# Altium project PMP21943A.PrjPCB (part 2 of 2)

## Sheet PMP21943A-Bias.SchDoc: Bias Supply
size 431 x 279 mm; Date: Not shown in title block; ApprovedBy: Not shown in title block; CheckedBy: Not shown in title block; Author: Not shown in title block; CompanyName: Not shown in title block; Engineer: Not shown in title block; Organization: Not shown in title block; Address1: Not shown in title block; Address2: Not shown in title block; Address3: Not shown in title block; Address4: Not shown in title block; DocumentNumber: 2; Revision: Use project parameter SCH_Rev; SheetNumber: 2; SheetTotal: 7; PageSetup: Record=PageOptions¦CenterHorizontal=True¦CenterVertical=True¦PrintScale=1.00¦XCorrection=1.00¦YCorrection=1.00¦PrintKind=0¦BorderSize=5000000¦LeftOffset=0¦BottomOffset=0¦Orientation=2¦PaperLength=1000¦PaperWidth=1000¦Scale=100¦PaperSource=15¦PrintQuality=600¦MediaType=1¦DitherType=10¦PaperKind=Letter¦PrintScaleMode=1
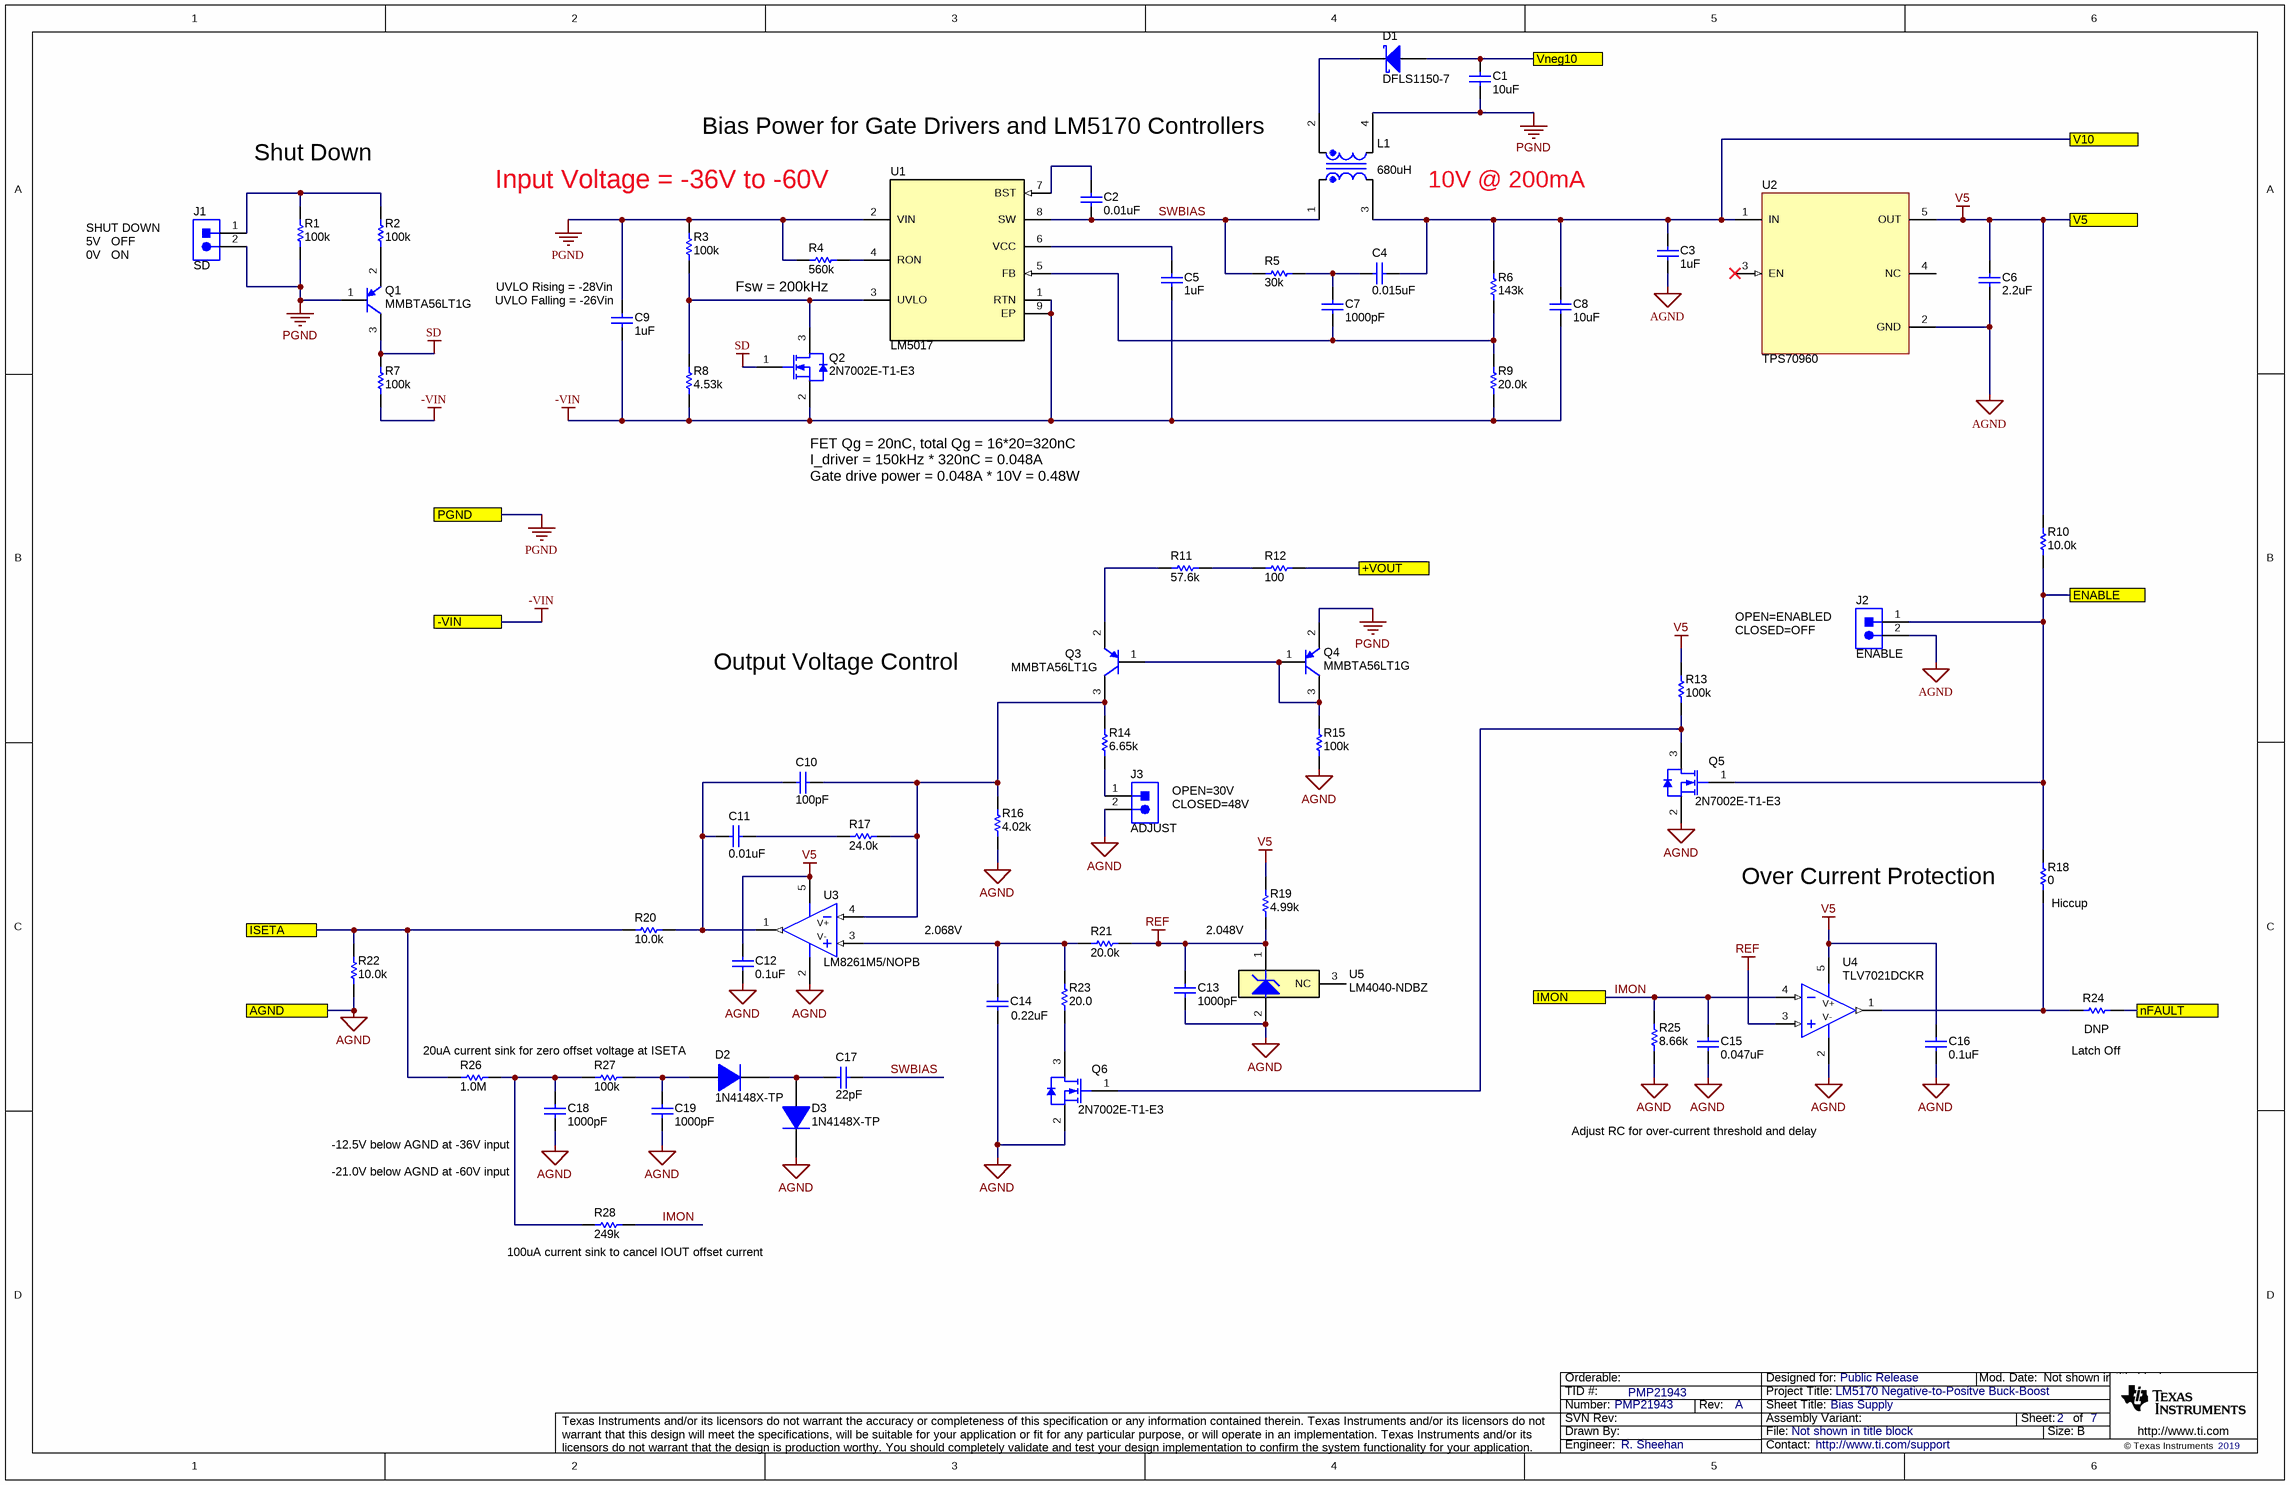
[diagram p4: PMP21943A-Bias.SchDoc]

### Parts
C1  ValueDisplayed: 10uF  [0805L]  (hidden comment: Capacitor)
C2  ValueDisplayed: 0.01uF  [0603L]  (hidden comment: Capacitor)
C3  ValueDisplayed: 1uF  [0805_HV]  (hidden comment: Capacitor)
C4  ValueDisplayed: 0.015uF  [0603L]  (hidden comment: Capacitor)
C5  ValueDisplayed: 1uF  [0603L]  (hidden comment: Capacitor)
C6  ValueDisplayed: 2.2uF  [0805_HV]  (hidden comment: Capacitor)
C7  ValueDisplayed: 1000pF  [0603L]  (hidden comment: Capacitor)
C8  ValueDisplayed: 10uF  [0805L]  (hidden comment: Capacitor)
C9  ValueDisplayed: 1uF  [1210_180L]  (hidden comment: Capacitor)
C10  ValueDisplayed: 100pF  [0603L]  (hidden comment: Capacitor)
C11  ValueDisplayed: 0.01uF  [0603L]  (hidden comment: Capacitor)
C12  ValueDisplayed: 0.1uF  [0603L]  (hidden comment: Capacitor)
C13  ValueDisplayed: 1000pF  [0603L]  (hidden comment: GRM188R72A102KA01D)
C14  ValueDisplayed: 0.22uF  [0603]  (hidden comment: C1608X7R1H224K080AB)
C15  ValueDisplayed: 0.047uF  [0603L]  (hidden comment: Capacitor)
C16  ValueDisplayed: 0.1uF  [0603L]  (hidden comment: Capacitor)
C17  ValueDisplayed: 22pF  [0603L]  (hidden comment: Capacitor)
C18  ValueDisplayed: 1000pF  [0603L]  (hidden comment: GRM188R72A102KA01D)
C19  ValueDisplayed: 1000pF  [0603L]  (hidden comment: GRM188R72A102KA01D)
D1  DFLS1150-7  [PowerDI123]
D2  1N4148X-TP  [SOD-523]
D3  1N4148X-TP  [SOD-523]
J1  SD  [Samtec_HTSW-102-07-G-S]
J2  ENABLE  [Samtec_HTSW-102-07-G-S]
J3  ADJUST  [Samtec_HTSW-102-07-G-S]
L1  ValueDisplayed: 680uH  [DRQ74]  (hidden comment: DRQ74-681-R)
Q1  MMBTA56LT1G  [SOT-23L]
Q2  2N7002E-T1-E3  [SOT-23]
Q3  MMBTA56LT1G  [SOT-23L]
Q4  MMBTA56LT1G  [SOT-23L]
Q5  2N7002E-T1-E3  [SOT-23]
Q6  2N7002E-T1-E3  [SOT-23]
R1  ValueDisplayed: 100k  [0603L]  (hidden comment: Resistor)
R2  ValueDisplayed: 100k  [0603L]  (hidden comment: Resistor)
R3  ValueDisplayed: 100k  [0603L]  (hidden comment: Resistor)
R4  ValueDisplayed: 560k  [0603L]  (hidden comment: Resistor)
R5  ValueDisplayed: 30k  [0603L]  (hidden comment: Resistor)
R6  ValueDisplayed: 143k  [0603L]  (hidden comment: Resistor)
R7  ValueDisplayed: 100k  [0603L]  (hidden comment: Resistor)
R8  ValueDisplayed: 4.53k  [0603L]  (hidden comment: Resistor)
R9  ValueDisplayed: 20.0k  [0603L]  (hidden comment: Resistor)
R10  ValueDisplayed: 10.0k  [0603L]  (hidden comment: Resistor)
R11  ValueDisplayed: 57.6k  [0603L]  (hidden comment: Resistor)
R12  ValueDisplayed: 100  [0603L]  (hidden comment: Resistor)
R13  ValueDisplayed: 100k  [0603L]  (hidden comment: Resistor)
R14  ValueDisplayed: 6.65k  [0603L]  (hidden comment: Resistor)
R15  ValueDisplayed: 100k  [0603L]  (hidden comment: Resistor)
R16  ValueDisplayed: 4.02k  [0603L]  (hidden comment: Resistor)
R17  ValueDisplayed: 24.0k  [0603L]  (hidden comment: Resistor)
R18  ValueDisplayed: 0  [0603L]  (hidden comment: Resistor)
R19  ValueDisplayed: 4.99k  [0603L]  (hidden comment: Resistor)
R20  ValueDisplayed: 10.0k  [0603L]  (hidden comment: Resistor)
R21  ValueDisplayed: 20.0k  [0603L]  (hidden comment: Resistor)
R22  ValueDisplayed: 10.0k  [0603L]  (hidden comment: Resistor)
R23  ValueDisplayed: 20.0  [0603L]  (hidden comment: Resistor)
R24  DNP  [0603L]
R25  ValueDisplayed: 8.66k  [0603L]  (hidden comment: Resistor)
R26  ValueDisplayed: 1.0M  [0603L]  (hidden comment: Resistor)
R27  ValueDisplayed: 100k  [0603L]  (hidden comment: Resistor)
R28  ValueDisplayed: 249k  [0603L]  (hidden comment: Resistor)
U1  LM5017  [DDA0008B_L]
U2  TPS70960  [DBV0005A_N]
U3  LM8261M5/NOPB  [DBV0005A_N]
U4  TLV7021DCKR  [DCK0005A_N]
U5  LM4040-NDBZ  [DBZ0003A_N]

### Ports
+VOUT, -VIN, AGND, ENABLE, IMON, ISETA, nFAULT, PGND, V5, V10, Vneg10

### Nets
+VOUT: R12.1 ; port +VOUT
-VIN: C5.2 C8.2 C9.2 Q2.2(S) R7.1 R8.2 R9.1 U1.1(RTN) U1.9(EP) ; port -VIN
AGND: C3.2 C6.2 C12.2 C13.2 C14.2 C15.2 C16.1 C18.2 C19.2 D3.1(K) J2.2 J3.2 Q5.2(S) Q6.2(S) R15.2 R16.2 R22.2 R25.1 U2.2(GND) U3.2(V-) U4.2(V-) U5.2(A) ; port AGND
PGND: C1.2 C9.1 J1.2 L1.4 Q1.1(B) Q4.2(E) R1.1 R3.1 R4.1 U1.2(VIN) ; port PGND
REF: C13.1 R19.2 R21.1 U4.3(IN+) U5.1(K)
SD: Q1.3(C) Q2.1(G) R7.2
V5: C6.1 C12.1 C16.2 R10.2 R13.1 R19.1 U2.5(OUT) U3.5(V+) U4.5(V+) ; port V5
V10: C3.1 C4.2 C8.1 L1.3 R6.2 U2.1(IN) ; port V10
ENABLE: J2.1 Q5.1(G) R10.1 R18.2 ; port ENABLE
IMON: C15.1 R25.2 R28.2 U4.4(IN-) ; port IMON
ISETA: R20.1 R22.1 R26.1 ; port ISETA
nFAULT: R24.1 ; port nFAULT
SWBIAS: C2.2 C17.1 L1.1 R5.2 U1.8(SW)
Vneg10: C1.1 D1.2(A) ; port Vneg10
NetC2_1: C2.1 U1.7(BST)
NetC4_1: C4.1 C7.2 R5.1
NetC5_1: C5.1 U1.6(VCC)
NetC7_1: C7.1 R6.1 R9.2 U1.5(FB)
NetC10_1: C10.1 Q3.3(C) R14.1 R16.1 R17.1 U3.4(IN-)
NetC10_2: C10.2 C11.1 R20.2 U3.1(OUT)
NetC11_2: C11.2 R17.2
NetC14_1: C14.1 R21.2 R23.2 U3.3(IN+)
NetC17_2: C17.2 D2.1(K) D3.2(A)
NetC18_1: C18.1 R26.2 R27.1 R28.1
NetC19_1: C19.1 D2.2(A) R27.2
NetD1_1: D1.1(K) L1.2
NetJ1_1: J1.1 R1.2 R2.2
NetJ3_1: J3.1 R14.2
NetQ1_2: Q1.2(E) R2.1
NetQ2_3: Q2.3(D) R3.2 R8.1 U1.3(UVLO)
NetQ3_1: Q3.1(B) Q4.1(B) Q4.3(C) R15.1
NetQ3_2: Q3.2(E) R11.2
NetQ5_3: Q5.3(D) Q6.1(G) R13.2
NetQ6_3: Q6.3(D) R23.1
NetR4_2: R4.2 U1.4(RON)
NetR11_1: R11.1 R12.2
NetR18_1: R18.1 R24.2 U4.1(OUT)

Not connected (* = marked no-connect by the designer): U2 3(EN)* 4(NC); U5 3(NC)

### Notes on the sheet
- Shut Down
- Bias Power for Gate Drivers and LM5170 Controllers
- Input Voltage = -36V to -60V
- 10V @ 200mA
- (near J1) SHUT DOWN
  5V   OFF
  0V   ON
- (near C9) UVLO Rising = -28Vin
- (near C9) UVLO Falling = -26Vin
- (near R4) Fsw = 200kHz
- FET Qg = 20nC, total Qg = 16*20=320nC
  I_driver = 150kHz * 320nC = 0.048A
  Gate drive power = 0.048A * 10V = 0.48W
- Output Voltage Control
- OPEN=ENABLED
  CLOSED=OFF
- OPEN=30V
  CLOSED=48V
- (near R18) Over Current Protection
- (near R18) Hiccup
- 2.068V
- (near R19) 2.048V
- 20uA current sink for zero offset voltage at ISETA
- (near R24) Latch Off
- -12.5V below AGND at -36V input
- -21.0V below AGND at -60V input
- Adjust RC for over-current threshold and delay
- (near R28) 100uA current sink to cancel IOUT offset current

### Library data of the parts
C1 C8 = CMP-0007995-2: CAP, CERM, 10 uF, 16 V, +/- 10%, X7R, 0805; PartNumber: CL21B106KOQNNNE; Manufacturer: Samsung Electro-Mechanics; Polarized: N; Value: 10uF; U/M: EA; Cap_F: 10µF; Value1: Unknown; VDC_V: 16V; TaMin_C: -55°C; TaMax_C: 125°C; Cap_Case: 0805; AEC Category: Q200; SizeArea_mm2: 2.5; SizeAreaWB_mm2: 6.75; SizeX_mm: 2; SizeY_mm: 1.25; SizeZ_mm: 1.45
C2 C11 = CMP-0007468-5: CAP, CERM, 0.01 uF, 100 V, +/- 10%, X7R, 0603; PartNumber: GRM188R72A103KA01D; Manufacturer: MuRata; Polarized: N; Value: 0.01uF; U/M: EA; Cap_F: 10nF; Value1: Unknown; VDC_V: 100V; TaMin_C: -55°C; TaMax_C: 125°C; Cap_Case: 0603; AEC Category: Q200; SizeArea_mm2: 1.28; SizeAreaWB_mm2: 4.68; SizeX_mm: 1.6; SizeY_mm: 0.8; SizeZ_mm: 1
C3 = CMP-0007891-2: CAP, CERM, 1 uF, 100 V, +/- 10%, X7S, 0805; PartNumber: C2012X7S2A105K125AB; Manufacturer: TDK; Polarized: N; Value: 1uF; U/M: EA; Cap_F: 1µF; ESR_ohm: 8.255m; Value1: 0.008255 ohm; VDC_V: 100V; IRMS_A: 2.27442A; TaMin_C: -55°C; TaMax_C: 125°C; Cap_Case: 0805; AEC Category: Q200; SizeArea_mm2: 2.5; SizeAreaWB_mm2: 6.75; SizeX_mm: 2; SizeY_mm: 1.25; SizeZ_mm: 1.45
C4 = CMP-0006883-4: CAP, CERM, 0.015 uF, 100 V, +/- 10%, X7R, 0603; PartNumber: C0603C153K1RACTU; Manufacturer: Kemet; Polarized: N; U/M: EA; Cap_F: 15nF; Value1: Unknown; VDC_V: 100V; TaMin_C: -55°C; TaMax_C: 125°C; Cap_Case: 0603; AEC Category: Q200; SizeArea_mm2: 1.28; SizeAreaWB_mm2: 4.68; SizeX_mm: 1.6; SizeY_mm: 0.8; SizeZ_mm: 1
C5 = CMP-0007379-4: CAP, CERM, 1 uF, 16 V, +/- 10%, X7R, 0603; PartNumber: GRM188R71C105KA12D; Manufacturer: MuRata; Polarized: N; Value: 1uF; U/M: EA; Cap_F: 1µF; ESR_ohm: 0.011; Value1: 0.011 ohm; VDC_V: 16V; TaMin_C: -55°C; TaMax_C: 125°C; Cap_Case: 0603; AEC Category: Q200; SizeArea_mm2: 1.28; SizeAreaWB_mm2: 4.68; SizeX_mm: 1.6; SizeY_mm: 0.8; SizeZ_mm: 1
C6 = CMP-0007867-2: CAP, CERM, 2.2 uF, 16 V, +/- 10%, X7R, 0805; PartNumber: C2012X7R1C225K125AB; Manufacturer: TDK; Polarized: N; Value: 2.2uF; U/M: EA; Cap_F: 2.2µF; ESR_ohm: 4.9m; Value1: 0.0049 ohm; VDC_V: 16V; TaMin_C: -55°C; TaMax_C: 125°C; Cap_Case: 0805; AEC Category: Q200; SizeArea_mm2: 2.5; SizeAreaWB_mm2: 6.75; SizeX_mm: 2; SizeY_mm: 1.25; SizeZ_mm: 1.45
C7 = CMP-0007467-4: CAP, CERM, 1000 pF, 100 V, +/- 10%, X7R, 0603; PartNumber: GRM188R72A102KA01D; Manufacturer: MuRata; Polarized: N; Value: 1000pF; U/M: EA; Cap_F: 1nF; Value1: Unknown; VDC_V: 100V; TaMin_C: -55°C; TaMax_C: 125°C; Cap_Case: 0603; AEC Category: Q200; SizeArea_mm2: 1.28; SizeAreaWB_mm2: 4.68; SizeX_mm: 1.6; SizeY_mm: 0.8; SizeZ_mm: 1
C9 = CMP-0009180-2: CAP, CERM, 1 uF, 100 V, +/- 10%, X7R, 1210; PartNumber: GRM32CR72A105KA35L; Manufacturer: MuRata; Polarized: N; Value: 1uF; U/M: EA; Cap_F: 1µF; Value1: Unknown; VDC_V: 100V; TaMin_C: -55°C; TaMax_C: 125°C; Cap_Case: 1210; AEC Category: Q200; SizeArea_mm2: 8; SizeAreaWB_mm2: 14.7; SizeX_mm: 3.2; SizeY_mm: 2.5; SizeZ_mm: 1.8
C10 = CMP-0006841-4: CAP, CERM, 100 pF, 50 V, +/- 5%, C0G/NP0, 0603; PartNumber: C0603C101J5GACTU; Manufacturer: Kemet; Polarized: N; Value: 100pF; U/M: EA; Value1: Unknown; VDC_V: 50V; TaMin_C: -55°C; TaMax_C: 125°C; Cap_Case: 0603; SizeArea_mm2: 1.28; SizeAreaWB_mm2: 4.68; SizeX_mm: 1.6; SizeY_mm: 0.8; SizeZ_mm: 1; AEC Category: Q200
C12 C16 = CMP-0007469-4: CAP, CERM, 0.1 uF, 100 V, +/- 10%, X7R, 0603; PartNumber: GRM188R72A104KA35D; Manufacturer: MuRata; Polarized: N; Value: 0.1uF; U/M: EA; Cap_F: 100nF; Value1: Unknown; VDC_V: 100V; TaMin_C: -55°C; TaMax_C: 125°C; Cap_Case: 0603; AEC Category: Q200; SizeArea_mm2: 1.28; SizeAreaWB_mm2: 4.68; SizeX_mm: 1.6; SizeY_mm: 0.8; SizeZ_mm: 1
C13 C18 C19 = CMP-0007467-4: CAP, CERM, 1000 pF, 100 V, +/- 10%, X7R, 0603; Manufacturer: MuRata; Polarized: N; Value: 1000pF; U/M: EA; Cap_F: 1nF; Value1: Unknown; VDC_V: 100V; TaMin_C: -55°C; TaMax_C: 125°C; Cap_Case: 0603; AEC Category: Q200; SizeArea_mm2: 1.28; SizeAreaWB_mm2: 4.68; SizeX_mm: 1.6; SizeY_mm: 0.8; SizeZ_mm: 1
C14 = CMP-0007047-4: CAP, CERM, 0.22 uF, 50 V, +/- 10%, X7R, 0603; Manufacturer: TDK; Polarized: N; Value: 0.22uF; U/M: EA; Cap_F: 220nF; ESR_ohm: 0.021699; Value1: 0.021699 ohm; VDC_V: 50V; IRMS_A: 1.12496A; TaMin_C: -55°C; TaMax_C: 125°C; AEC Category: Q200; SizeArea_mm2: 1.28; SizeAreaWB_mm2: 4.68; SizeX_mm: 1.6; SizeY_mm: 0.8; SizeZ_mm: 1
C15 = CMP-0007457-4: CAP, CERM, 0.047 uF, 50 V, +/- 10%, X7R, 0603; PartNumber: GRM188R71H473KA61D; Manufacturer: MuRata; Polarized: N; U/M: EA; Cap_F: 47nF; Value1: Unknown; VDC_V: 50V; TaMin_C: -55°C; TaMax_C: 125°C; Cap_Case: 0603; SizeArea_mm2: 1.28; SizeAreaWB_mm2: 4.68; SizeX_mm: 1.6; SizeY_mm: 0.8; SizeZ_mm: 1; AEC Category: Q200
C17 = CMP-0007196-4: CAP, CERM, 22 pF, 50 V, +/- 5%, C0G/NP0, 0603; PartNumber: GRM1885C1H220JA01D; Manufacturer: MuRata; Polarized: N; Value: 22pF; U/M: EA; Value1: Unknown; VDC_V: 50V; TaMin_C: -55°C; TaMax_C: 125°C; Cap_Case: 0603; SizeArea_mm2: 1.28; SizeAreaWB_mm2: 4.68; SizeX_mm: 1.6; SizeY_mm: 0.8; SizeZ_mm: 1; AEC Category: Q200
D1 = CMP-0077034-2: Diode, Schottky, 150 V, 1 A, PowerDI123; Manufacturer: Diodes Inc.; Vf_V: 820mV; Value: 150V; Value1: 1A; Value2: 0.82V; TJmax_C: 175°C; SizeAreaWB_mm2: 13.066; SizeArea_mm2: 6.586; SizeX_mm: 3.7; SizeY_mm: 1.78; SizeZ_mm: 0.98; AEC Category: Q101; Green_Lifecycle: Active; Green_REACh: Passed
D2 D3 = CMP-0076957-3: Diode, Switching, 75 V, 0.3 A, SOD-523; Manufacturer: Micro Commercial Components; Vf_V: 1.25V; Value: 75V; Value1: 0.3A; Io_A: 300mA; TJmax_C: 150°C; AEC Category: Q101; Green_Lifecycle: Not Set; Green_REACh: Incomplete; SizeArea_mm2: 1.53; SizeAreaWB_mm2: 5.13; SizeX_mm: 1.7; SizeY_mm: 0.9; SizeZ_mm: 0.65
J1-J3 = CMP-0075483-1: Header, 100mil, 2x1, Gold, TH; PartNumber: HTSW-102-07-G-S; Manufacturer: Samtec; Green_Lifecycle: Active; Green_REACh: Passed; CNHeader: True; CT: False
L1 = CMP-0012798-2: Coupled inductor, 680 uH, 0.38 A, 5.15 ohm, SMD; Manufacturer: Coiltronics; Value: 680uH; Ind_H: 680µH; DCR_ohm: 5.15; SizeAreaWB_mm2: 92.16; SizeArea_mm2: 57.76; SizeX_mm: 7.6; SizeZ_mm: 4.45
Q1 Q3 Q4 = CMP-0000338-2: Transistor, PNP, 80 V, 0.5 A, SOT-23; Manufacturer: ON Semiconductor; CompType: BJT; PNP: 1; NPN: 0; Vceo_V: 80V; Vcesat1_V: 2.5dV; Value: 80 V; IcRated_A: 5dA; Value1: 0.5 A; TaMin_C: -55°C; TaMax_C: 150°C; U/M: EA; AEC Category: Q101; SizeArea_mm2: 7.5; SizeAreaWB_mm2: 14; SizeX_mm: 2.5; SizeY_mm: 3; SizeZ_mm: 1.1
Q2 = CMP-0000771-1: MOSFET, N-CH, 60 V, 0.24 A, SOT-23; Manufacturer: Vishay-Siliconix; Alternate Manufacturer: None; U/M: EA; ChType: N; Value: 60V; Value1: 1; Rdson45_ohm: 1.8; Value2: 0.4 nC; QgTyp_nC: 0.4; Vgs_V: 20V; IdsMax_A: 2.4dA; SizeAreaWB_mm2: 14; SizeArea_mm2: 7.5; SizeX_mm: 2.5; SizeY_mm: 3; SizeZ_mm: 1.1; AEC Category: Q101
Q5 Q6 = CMP-0000771-1: MOSFET, N-CH, 60 V, 0.24 A, SOT-23; Manufacturer: Vishay-Siliconix; Alternate Manufacturer: None; U/M: EA; ChType: N; Value: 60V; Value1: 1; Rdson45_ohm: 1.8; Value2: 0.4 nC; QgTyp_nC: 0.4; Vgs_V: 20V; IdsMax_A: 2.4dA; AEC Category: Q101; SizeArea_mm2: 7.5; SizeAreaWB_mm2: 14; SizeX_mm: 2.5; SizeY_mm: 3; SizeZ_mm: 1.1
R1 R2 R7 R15 = CMP-0025698-4: RES, 100 k, 5%, 0.1 W, AEC-Q200 Grade 0, 0603; PartNumber: CRCW0603100KJNEA; Manufacturer: Vishay-Dale; Value: 100k; Power_W: 100mW; Value2: 0.1W; VDC_V: 75V; TempCo: 200 ppm/C; EIA_Code: E24; AEC Category: Q200; AEC Qualified: Y; AEC Grade: 0; SizeArea_mm2: 1.28; SizeX_mm: 1.6; SizeY_mm: 0.8; SizeZ_mm: 1
R3 R13 = CMP-0021990-4: RES, 100 k, 1%, 0.1 W, AEC-Q200 Grade 0, 0603; PartNumber: CRCW0603100KFKEA; Manufacturer: Vishay-Dale; Value: 100k; Power_W: 100mW; Value2: 0.1W; VDC_V: 75V; TempCo: 100 ppm/C; EIA_Code: E96; AEC Category: Q200; AEC Qualified: Y; AEC Grade: 0; SizeArea_mm2: 1.28; SizeX_mm: 1.6; SizeY_mm: 0.8; SizeZ_mm: 1
R4 = CMP-0022496-4: RES, 560 k, 1%, 0.1 W, AEC-Q200 Grade 0, 0603; PartNumber: CRCW0603560KFKEA; Manufacturer: Vishay-Dale; Value: 560k; Power_W: 100mW; Value2: 0.1W; VDC_V: 75V; TempCo: 100 ppm/C; AEC Category: Q200; AEC Qualified: Y; AEC Grade: 0; SizeArea_mm2: 1.28; SizeX_mm: 1.6; SizeY_mm: 0.8; SizeZ_mm: 1
R5 = CMP-0025782-4: RES, 30 k, 5%, 0.1 W, AEC-Q200 Grade 0, 0603; PartNumber: CRCW060330K0JNEA; Manufacturer: Vishay-Dale; Value: 30k; Value_Code: 30k0; Power_W: 100mW; Value2: 0.1W; VDC_V: 75V; TempCo: 200 ppm/C; EIA_Code: E24; AEC Category: Q200; AEC Qualified: Y; AEC Grade: 0; SizeArea_mm2: 1.28; SizeX_mm: 1.6; SizeY_mm: 0.8; SizeZ_mm: 1
R6 = CMP-0022050-4: RES, 143 k, 1%, 0.1 W, AEC-Q200 Grade 0, 0603; PartNumber: CRCW0603143KFKEA; Manufacturer: Vishay-Dale; Value: 143k; Power_W: 100mW; Value2: 0.1W; VDC_V: 75V; TempCo: 100 ppm/C; EIA_Code: E96; AEC Category: Q200; AEC Qualified: Y; AEC Grade: 0; SizeArea_mm2: 1.28; SizeX_mm: 1.6; SizeY_mm: 0.8; SizeZ_mm: 1
R8 = CMP-0022454-4: RES, 4.53 k, 1%, 0.1 W, AEC-Q200 Grade 0, 0603; PartNumber: CRCW06034K53FKEA; Manufacturer: Vishay-Dale; Value: 4.53k; Value_Code: 4k53; Power_W: 100mW; Value2: 0.1W; VDC_V: 75V; TempCo: 100 ppm/C; EIA_Code: E96; AEC Category: Q200; AEC Qualified: Y; AEC Grade: 0; SizeArea_mm2: 1.28; SizeX_mm: 1.6; SizeY_mm: 0.8; SizeZ_mm: 1
R9 = CMP-0022204-4: RES, 20.0 k, 1%, 0.1 W, AEC-Q200 Grade 0, 0603; PartNumber: CRCW060320K0FKEA; Manufacturer: Vishay-Dale; Value: 20.0k; Res_ohm: 20k; Value_Code: 20k0; Power_W: 100mW; Value2: 0.1W; VDC_V: 75V; TempCo: 100 ppm/C; EIA_Code: E96; AEC Category: Q200; AEC Qualified: Y; AEC Grade: 0; SizeArea_mm2: 1.28; SizeX_mm: 1.6; SizeY_mm: 0.8; SizeZ_mm: 1
R10 R20 = CMP-0021998-4: RES, 10.0 k, 1%, 0.1 W, AEC-Q200 Grade 0, 0603; PartNumber: CRCW060310K0FKEA; Manufacturer: Vishay-Dale; Value: 10.0k; Res_ohm: 10k; Value_Code: 10k0; Power_W: 100mW; Value2: 0.1W; VDC_V: 75V; TempCo: 100 ppm/C; EIA_Code: E96; AEC Category: Q200; AEC Grade: 0; AEC Qualified: Y; SizeArea_mm2: 1.28; SizeX_mm: 1.6; SizeY_mm: 0.8; SizeZ_mm: 1
R11 = CMP-0022503-4: RES, 57.6 k, 1%, 0.1 W, AEC-Q200 Grade 0, 0603; PartNumber: CRCW060357K6FKEA; Manufacturer: Vishay-Dale; Value: 57.6k; Value_Code: 57k6; Power_W: 100mW; Value2: 0.1W; VDC_V: 75V; TempCo: 100 ppm/C; EIA_Code: E96; AEC Category: Q200; AEC Qualified: Y; AEC Grade: 0; SizeArea_mm2: 1.28; SizeX_mm: 1.6; SizeY_mm: 0.8; SizeZ_mm: 1
R12 = CMP-0021991-4: RES, 100, 1%, 0.1 W, AEC-Q200 Grade 0, 0603; PartNumber: CRCW0603100RFKEA; Manufacturer: Vishay-Dale; Value: 100; Value_Code: 100R; Power_W: 100mW; Value2: 0.1W; VDC_V: 75V; TempCo: 100 ppm/C; EIA_Code: E96; SizeArea_mm2: 1.28; SizeX_mm: 1.6; SizeY_mm: 0.8; SizeZ_mm: 1; AEC Category: Q200; AEC Qualified: Y; AEC Grade: 0
R14 = CMP-0022562-4: RES, 6.65 k, 1%, 0.1 W, AEC-Q200 Grade 0, 0603; PartNumber: CRCW06036K65FKEA; Manufacturer: Vishay-Dale; Value: 6.65k; Value_Code: 6k65; Power_W: 100mW; Value2: 0.1W; VDC_V: 75V; TempCo: 100 ppm/C; EIA_Code: E96; AEC Category: Q200; AEC Qualified: Y; AEC Grade: 0; SizeArea_mm2: 1.28; SizeX_mm: 1.6; SizeY_mm: 0.8; SizeZ_mm: 1
R16 = CMP-0022449-4: RES, 4.02 k, 1%, 0.1 W, AEC-Q200 Grade 0, 0603; PartNumber: CRCW06034K02FKEA; Manufacturer: Vishay-Dale; Value: 4.02k; Value_Code: 4k02; Power_W: 100mW; Value2: 0.1W; VDC_V: 75V; TempCo: 100 ppm/C; EIA_Code: E96; AEC Category: Q200; AEC Qualified: Y; AEC Grade: 0; SizeArea_mm2: 1.28; SizeX_mm: 1.6; SizeY_mm: 0.8; SizeZ_mm: 1
R17 = CMP-0022945-5: RES, 24.0 k, 1%, 0.1 W, 0603; PartNumber: RC0603FR-0724KL; Manufacturer: Yageo; Value: 24.0k; Res_ohm: 24k; Value_Code: 24k0; Power_W: 100mW; Value2: 0.1W; VDC_V: 75V; TempCo: 100 ppm/C; AEC Category: Q200; AEC Qualified: N; SizeArea_mm2: 1.28; SizeX_mm: 1.6; SizeY_mm: 0.8; SizeZ_mm: 1; SizeAreaWB_mm2: 4.68
R18 = CMP-0025697-4: RES, 0, 5%, 0.1 W, AEC-Q200 Grade 0, 0603; PartNumber: CRCW06030000Z0EA; Manufacturer: Vishay-Dale; Value: 0; Value_Code: 0000; Power_W: 100mW; Value2: 0.1W; VDC_V: 75V; TempCo: 200 ppm/C; EIA_Code: E24; SizeArea_mm2: 1.28; SizeX_mm: 1.6; SizeY_mm: 0.8; SizeZ_mm: 1; AEC Category: Q200; AEC Qualified: Y
R19 = CMP-0022458-4: RES, 4.99 k, 1%, 0.1 W, AEC-Q200 Grade 0, 0603; PartNumber: CRCW06034K99FKEA; Manufacturer: Vishay-Dale; Value: 4.99k; Value_Code: 4k99; Power_W: 100mW; Value2: 0.1W; VDC_V: 75V; TempCo: 100 ppm/C; EIA_Code: E96; AEC Category: Q200; AEC Grade: 0; AEC Qualified: Y; SizeArea_mm2: 1.28; SizeX_mm: 1.6; SizeY_mm: 0.8; SizeZ_mm: 1
R21 = CMP-0022204-4: RES, 20.0 k, 1%, 0.1 W, AEC-Q200 Grade 0, 0603; PartNumber: CRCW060320K0FKEA; Manufacturer: Vishay-Dale; Value: 20.0k; Res_ohm: 20k; Value_Code: 20k0; Power_W: 100mW; Value2: 0.1W; VDC_V: 75V; TempCo: 100 ppm/C; EIA_Code: E96; SizeArea_mm2: 1.28; SizeX_mm: 1.6; SizeY_mm: 0.8; SizeZ_mm: 1; AEC Category: Q200; AEC Qualified: Y; AEC Grade: 0
R22 = CMP-0021998-4: RES, 10.0 k, 1%, 0.1 W, AEC-Q200 Grade 0, 0603; PartNumber: CRCW060310K0FKEA; Manufacturer: Vishay-Dale; Value: 10.0k; Res_ohm: 10k; Value_Code: 10k0; Power_W: 100mW; Value2: 0.1W; VDC_V: 75V; TempCo: 100 ppm/C; EIA_Code: E96; AEC Category: Q200; AEC Qualified: Y; AEC Grade: 0; SizeArea_mm2: 1.28; SizeX_mm: 1.6; SizeY_mm: 0.8; SizeZ_mm: 1
R23 = CMP-0022206-4: RES, 20.0, 1%, 0.1 W, AEC-Q200 Grade 0, 0603; PartNumber: CRCW060320R0FKEA; Manufacturer: Vishay-Dale; Value: 20.0; Res_ohm: 20; Value_Code: 20R0; Power_W: 100mW; Value2: 0.1W; VDC_V: 75V; TempCo: 100 ppm/C; EIA_Code: E96; AEC Category: Q200; AEC Grade: 0; AEC Qualified: Y; SizeArea_mm2: 1.28; SizeX_mm: 1.6; SizeY_mm: 0.8; SizeZ_mm: 1
R24 = CMP-0025697-4: RES, 0, 5%, 0.1 W, AEC-Q200 Grade 0, 0603; PartNumber: CRCW06030000Z0EA; Manufacturer: Vishay-Dale; CompType: Resistor; Value: 0; Value_Code: 0000; Power_W: 100mW; Value2: 0.1W; VDC_V: 75V; TempCo: 200 ppm/C; EIA_Code: E24; SizeArea_mm2: 1.28; SizeX_mm: 1.6; SizeY_mm: 0.8; SizeZ_mm: 1; AEC Category: Q200; AEC Qualified: Y
R25 = CMP-0022637-4: RES, 8.66 k, 1%, 0.1 W, AEC-Q200 Grade 0, 0603; PartNumber: CRCW06038K66FKEA; Manufacturer: Vishay-Dale; Value: 8.66k; Value_Code: 8k66; Power_W: 100mW; Value2: 0.1W; VDC_V: 75V; TempCo: 100 ppm/C; EIA_Code: E96; SizeArea_mm2: 1.28; SizeX_mm: 1.6; SizeY_mm: 0.8; SizeZ_mm: 1; AEC Category: Q200; AEC Qualified: Y; AEC Grade: 0
R26 = CMP-0025736-4: RES, 1.0 M, 5%, 0.1 W, AEC-Q200 Grade 0, 0603; PartNumber: CRCW06031M00JNEA; Manufacturer: Vishay-Dale; Value: 1.0Meg; Res_ohm: 1M; Value_Code: 1M00; Power_W: 100mW; Value2: 0.1W; VDC_V: 75V; TempCo: 200 ppm/C; EIA_Code: E24; SizeArea_mm2: 1.28; SizeX_mm: 1.6; SizeY_mm: 0.8; SizeZ_mm: 1; AEC Category: Q200; AEC Qualified: Y; AEC Grade: 0
R27 = CMP-0021990-4: RES, 100 k, 1%, 0.1 W, AEC-Q200 Grade 0, 0603; PartNumber: CRCW0603100KFKEA; Manufacturer: Vishay-Dale; Value: 100k; Power_W: 100mW; Value2: 0.1W; VDC_V: 75V; TempCo: 100 ppm/C; EIA_Code: E96; SizeArea_mm2: 1.28; SizeX_mm: 1.6; SizeY_mm: 0.8; SizeZ_mm: 1; AEC Category: Q200; AEC Qualified: Y; AEC Grade: 0
R28 = CMP-0022234-4: RES, 249 k, 1%, 0.1 W, AEC-Q200 Grade 0, 0603; PartNumber: CRCW0603249KFKEA; Manufacturer: Vishay-Dale; Value: 249k; Power_W: 100mW; Value2: 0.1W; VDC_V: 75V; TempCo: 100 ppm/C; EIA_Code: E96; SizeArea_mm2: 1.28; SizeX_mm: 1.6; SizeY_mm: 0.8; SizeZ_mm: 1; AEC Category: Q200; AEC Qualified: Y; AEC Grade: 0
U1 = CMP-0066088-2: 7.5-100V Wide Vin, 300mA Constant On-Time Synchronous Buck Regulator, DDA0008B (SOIC-8); PartNumber: LM5018MRX/NOPB; Alternate PartNumber: LM5018MR/NOPB; Manufacturer: Texas Instruments; CompType: IC; U/M: EA; SizeArea_mm2: 31.0; SizeAreaWB_mm2: 57.4; SizeX_mm: 5.0; SizeY_mm: 6.2; SizeZ_mm: 1.7
U2 = CMP-0066783-1: 150-mA, 30-V, Ultra-Low IQ, Wide Input Low-Dropout Regulator with Reverse Current Protection, DBV0005A (SOT-23-5); PartNumber: TPS70950DBVR; Alternate PartNumber: TPS70950DBVT; Manufacturer: Texas Instruments; CompType: IC; U/M: EA; Green_Lifecycle: Active; Green_REACh: Passed; SizeArea_mm2: 8.12; SizeAreaWB_mm2: 14.82; SizeX_mm: 2.8; SizeY_mm: 2.9; SizeZ_mm: 1.45
U3 = CMP-0068647-3: RRIO, High Output Current & Unlimited Cap Load Op Amp, DBV0005A (SOT-23-5); Manufacturer: Texas Instruments; CompType: IC; Rating: Catalog; SizeArea_mm2: 8.12; AEC Qualified: N; SizeZ_mm: 1.45; SizeAreaWB_mm2: 14.82; SizeY_mm: 2.9; AEC Category: Q200; SizeX_mm: 2.8
U4 = CMP-0085889-2: Small-Size Micropower Low-Voltage Comparator, DCK0005A (SOT-SC70-5); Manufacturer: Texas Instruments; Alternate PartNumber: TLV7021DCKT; SizeAreaWB_mm2: 9.3; SizeY_mm: 2; Rating: Catalog; SizeZ_mm: 1.1; SizeX_mm: 2.1; CompType: IC; AEC Qualified: N; SizeArea_mm2: 4.2; AEC Category: Q200
U5 = CMP-0078976-1: Precision Micropower Shunt Voltage Reference, DBZ0003A (SOT-23-3); PartNumber: LM4040AIM3-2.0/NOPB; Manufacturer: Texas Instruments; Alternate PartNumber: LM4040AIM3X-2.0/NOPB; CompType: IC; AEC Category: Q200; AEC Qualified: N; Green_Lifecycle: Active; Green_REACh: Passed; SizeArea_mm2: 7.5; SizeAreaWB_mm2: 14; SizeX_mm: 2.5; SizeY_mm: 3; SizeZ_mm: 1.12

## Sheet PMP21943A-Controller2.SchDoc: Controller
size 431 x 279 mm; Date: Not shown in title block; ApprovedBy: Not shown in title block; CheckedBy: Not shown in title block; Author: Not shown in title block; CompanyName: Not shown in title block; Engineer: Not shown in title block; Organization: Not shown in title block; Address1: Not shown in title block; Address2: Not shown in title block; Address3: Not shown in title block; Address4: Not shown in title block; DocumentNumber: 4; Revision: Use project parameter SCH_Rev; SheetNumber: 4; SheetTotal: 7; PageSetup: Record=PageOptions¦CenterHorizontal=True¦CenterVertical=True¦PrintScale=1.00¦XCorrection=1.00¦YCorrection=1.00¦PrintKind=0¦BorderSize=5000000¦LeftOffset=0¦BottomOffset=0¦Orientation=2¦PaperLength=1000¦PaperWidth=1000¦Scale=100¦PaperSource=15¦PrintQuality=600¦MediaType=1¦DitherType=10¦PaperKind=Letter¦PrintScaleMode=1
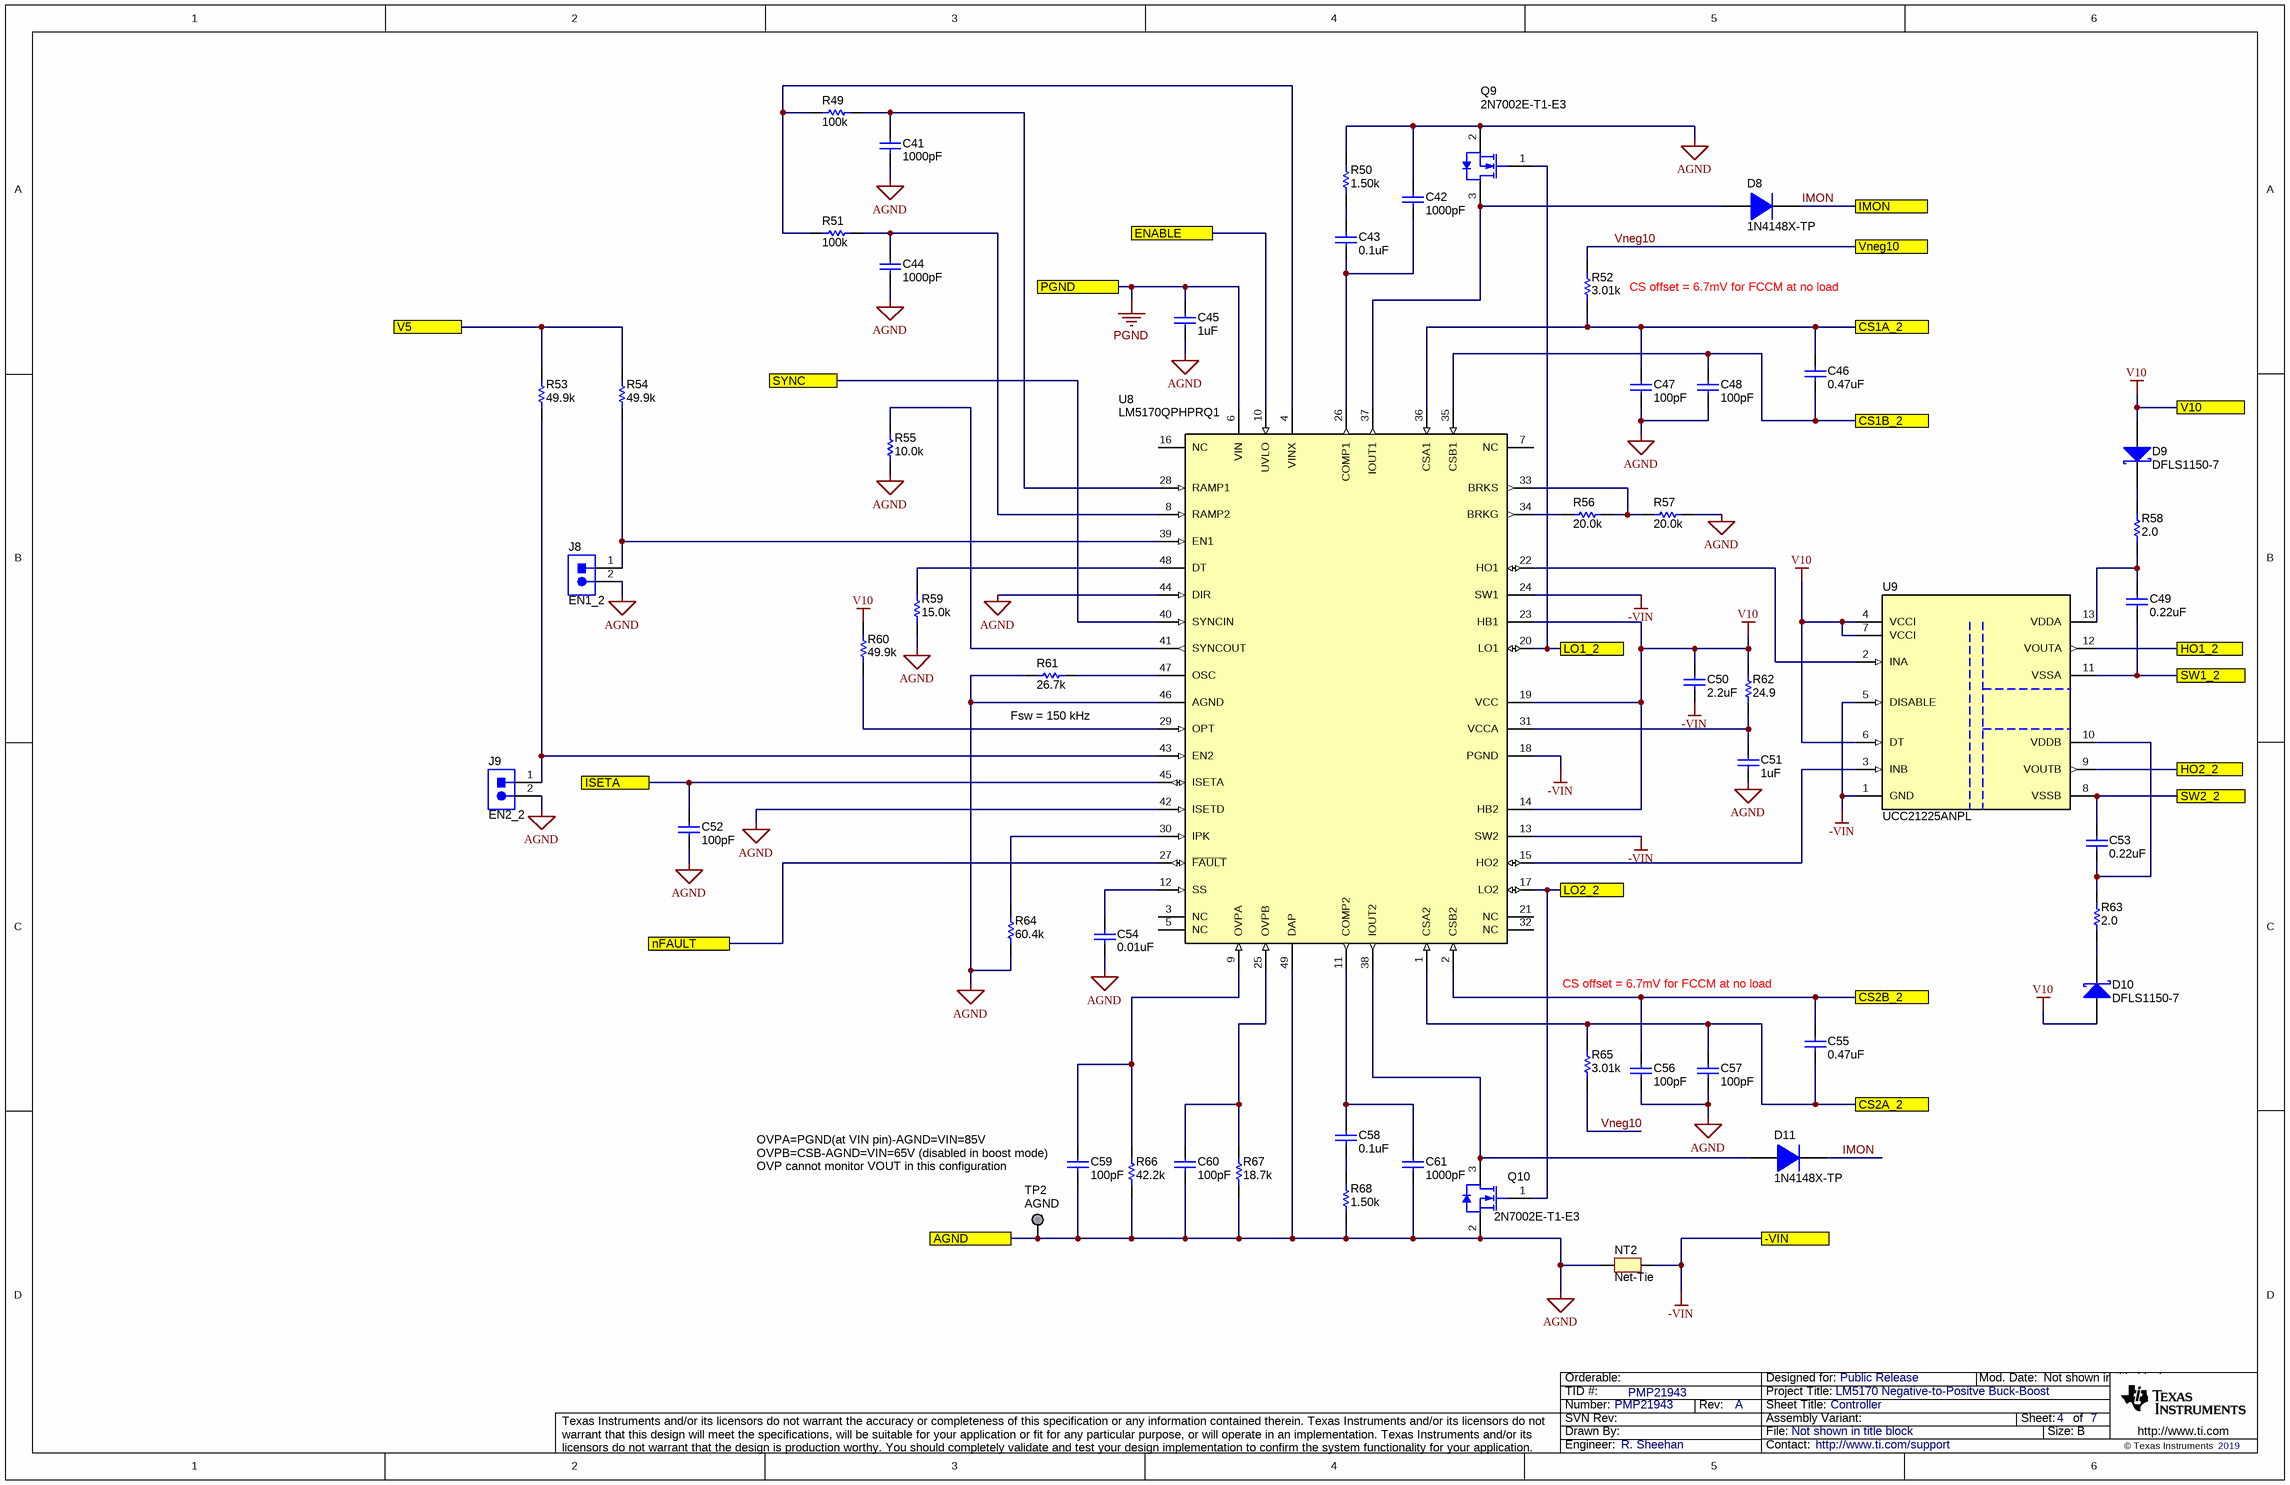
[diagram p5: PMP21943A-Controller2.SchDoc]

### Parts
C41  ValueDisplayed: 1000pF  [0603L]  (hidden comment: Capacitor)
C42  ValueDisplayed: 1000pF  [0603L]  (hidden comment: GRM188R72A102KA01D)
C43  ValueDisplayed: 0.1uF  [0603L]  (hidden comment: GRM188R72A104KA35D)
C44  ValueDisplayed: 1000pF  [0603L]  (hidden comment: Capacitor)
C45  ValueDisplayed: 1uF  [0805_HV]  (hidden comment: Capacitor)
C46  ValueDisplayed: 0.47uF  [0603L]  (hidden comment: GRM188R71C474KA88D)
C47  ValueDisplayed: 100pF  [0603L]  (hidden comment: Capacitor)
C48  ValueDisplayed: 100pF  [0603L]  (hidden comment: Capacitor)
C49  ValueDisplayed: 0.22uF  [0603L]  (hidden comment: C1608X7R1H224K080AB)
C50  ValueDisplayed: 2.2uF  [0805_HV]  (hidden comment: Capacitor)
C51  ValueDisplayed: 1uF  [0603L]  (hidden comment: Capacitor)
C52  ValueDisplayed: 100pF  [0603L]  (hidden comment: Capacitor)
C53  ValueDisplayed: 0.22uF  [0603L]  (hidden comment: Capacitor)
C54  ValueDisplayed: 0.01uF  [0603L]  (hidden comment: Capacitor)
C55  ValueDisplayed: 0.47uF  [0603L]  (hidden comment: GRM188R71C474KA88D)
C56  ValueDisplayed: 100pF  [0603L]  (hidden comment: Capacitor)
C57  ValueDisplayed: 100pF  [0603L]  (hidden comment: Capacitor)
C58  ValueDisplayed: 0.1uF  [0603L]  (hidden comment: GRM188R72A104KA35D)
C59  ValueDisplayed: 100pF  [0603L]  (hidden comment: Capacitor)
C60  ValueDisplayed: 100pF  [0603L]  (hidden comment: Capacitor)
C61  ValueDisplayed: 1000pF  [0603L]  (hidden comment: GRM188R72A102KA01D)
D8  1N4148X-TP  [SOD-523]
D9  DFLS1150-7  [PowerDI123]
D10  DFLS1150-7  [PowerDI123]
D11  1N4148X-TP  [SOD-523]
J8  EN1_2  [Samtec_HTSW-102-07-G-S]
J9  EN2_2  [Samtec_HTSW-102-07-G-S]
NT2  Net-Tie  [Net-Tie_10mil]  (net tie, no BOM)
Q9  2N7002E-T1-E3  [SOT-23]
Q10  2N7002E-T1-E3  [SOT-23]
R49  ValueDisplayed: 100k  [0603L]  (hidden comment: Resistor)
R50  ValueDisplayed: 1.50k  [0603L]  (hidden comment: CRCW06031K50FKEA)
R51  ValueDisplayed: 100k  [0603L]  (hidden comment: Resistor)
R52  ValueDisplayed: 3.01k  [0603]  (hidden comment: CRCW06033K01FKEA)
R53  ValueDisplayed: 49.9k  [0603L]  (hidden comment: Resistor)
R54  ValueDisplayed: 49.9k  [0603L]  (hidden comment: Resistor)
R55  ValueDisplayed: 10.0k  [0603L]  (hidden comment: Resistor)
R56  ValueDisplayed: 20.0k  [0603L]  (hidden comment: Resistor)
R57  ValueDisplayed: 20.0k  [0603L]  (hidden comment: Resistor)
R58  ValueDisplayed: 2.0  [0603L]  (hidden comment: Resistor)
R59  ValueDisplayed: 15.0k  [0603L]  (hidden comment: Resistor)
R60  ValueDisplayed: 49.9k  [0603L]  (hidden comment: Resistor)
R61  ValueDisplayed: 26.7k  [0603L]  (hidden comment: Resistor)
R62  ValueDisplayed: 24.9  [0603L]  (hidden comment: CRCW060324R9FKEA)
R63  ValueDisplayed: 2.0  [0603L]  (hidden comment: Resistor)
R64  ValueDisplayed: 60.4k  [0603]  (hidden comment: CRCW060360K4FKEA)
R65  ValueDisplayed: 3.01k  [0603]  (hidden comment: CRCW06033K01FKEA)
R66  ValueDisplayed: 42.2k  [0603L]  (hidden comment: Resistor)
R67  ValueDisplayed: 18.7k  [0603L]  (hidden comment: Resistor)
R68  ValueDisplayed: 1.50k  [0603L]  (hidden comment: CRCW06031K50FKEA)
TP2  AGND  [Keystone1598-2]
U8  PartNumber: LM5170QPHPRQ1  [PHP0048D_L]  (hidden comment: CMP-0013575-3)
U9  UCC21225ANPL  [NPL0013A]

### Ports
-VIN, AGND, CS1A_2, CS1B_2, CS2A_2, CS2B_2, ENABLE, HO1_2, HO2_2, IMON, ISETA, LO1_2, LO2_2, nFAULT, PGND, SW1_2, SW2_2, SYNC, V5, V10, Vneg10

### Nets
-VIN: C50.2 NT2.2 U8.13(SW2) U8.18(PGND) U8.24(SW1) U9.1(GND) U9.5(DISABLE) ; port -VIN
AGND: C41.2 C42.1 C44.2 C45.2 C47.2 C48.2 C51.2 C52.2 C54.2 C56.2 C57.2 C59.2 C60.2 C61.2 J8.2 J9.2 NT2.1 Q9.2(S) Q10.2(S) R50.2 R55.2 R57.1 R59.1 R61.1 R64.1 R66.1 R67.1 R68.1 TP2.1 U8.42(ISETD) U8.44(DIR) U8.46(AGND) U8.49(DAP) ; port AGND
PGND: C45.1 U8.6(VIN) ; port PGND
V5: R53.2 R54.2 ; port V5
V10: C50.1 D9.2(A) D10.2(A) R60.2 R62.2 U8.14(HB2) U8.19(VCC) U8.23(HB1) U9.4(VCCI) U9.6(DT) U9.7(VCCI) ; port V10
CS1A_2: C46.1 C47.1 R52.1 U8.36(CSA1) ; port CS1A_2
CS1B_2: C46.2 C48.1 U8.35(CSB1) ; port CS1B_2
CS2A_2: C55.2 C57.1 R65.2 U8.1(CSA2) ; port CS2A_2
CS2B_2: C55.1 C56.1 U8.2(CSB2) ; port CS2B_2
ENABLE: U8.10(UVLO) ; port ENABLE
HO1_2: U9.12(VOUTA) ; port HO1_2
HO2_2: U9.9(VOUTB) ; port HO2_2
IMON: D8.1(K) D11.1(K) ; port IMON
ISETA: C52.1 U8.45(ISETA) ; port ISETA
LO1_2: Q9.1(G) U8.20(LO1) ; port LO1_2
LO2_2: Q10.1(G) U8.17(LO2) ; port LO2_2
nFAULT: U8.27(~{FAULT}) ; port nFAULT
SW1_2: C49.1 U9.11(VSSA) ; port SW1_2
SW2_2: C53.2 U9.8(VSSB) ; port SW2_2
SYNC: U8.40(SYNCIN) ; port SYNC
Vneg10: R52.2 R65.1 ; port Vneg10
NetC41_1: C41.1 R49.2 U8.28(RAMP1)
NetC42_2: C42.2 C43.2 U8.26(COMP1)
NetC43_1: C43.1 R50.1
NetC44_1: C44.1 R51.2 U8.8(RAMP2)
NetC49_2: C49.2 R58.1 U9.13(VDDA)
NetC51_1: C51.1 R62.1 U8.31(VCCA)
NetC53_1: C53.1 R63.1 U9.10(VDDB)
NetC54_1: C54.1 U8.12(SS)
NetC58_1: C58.1 C61.1 U8.11(COMP2)
NetC58_2: C58.2 R68.2
NetC59_1: C59.1 R66.2 U8.9(OVPA)
NetC60_1: C60.1 R67.2 U8.25(OVPB)
NetD8_2: D8.2(A) Q9.3(D) U8.37(IOUT1)
NetD9_1: D9.1(K) R58.2
NetD10_1: D10.1(K) R63.2
NetD11_2: D11.2(A) Q10.3(D) U8.38(IOUT2)
NetJ8_1: J8.1 R54.1 U8.39(EN1)
NetJ9_1: J9.1 R53.1 U8.43(EN2)
NetR49_1: R49.1 R51.1 U8.4(VINX)
NetR55_1: R55.1 U8.41(SYNCOUT)
NetR56_1: R56.1 R57.2 U8.33(BRKS)
NetR56_2: R56.2 U8.34(BRKG)
NetR59_2: R59.2 U8.48(DT)
NetR60_1: R60.1 U8.29(OPT)
NetR61_2: R61.2 U8.47(OSC)
NetR64_2: R64.2 U8.30(IPK)
NetU8_15: U8.15(HO2) U9.3(INB)
NetU8_22: U8.22(HO1) U9.2(INA)

Not connected (* = marked no-connect by the designer): U8 3(NC) 5(NC) 7(NC) 16(NC) 21(NC) 32(NC)

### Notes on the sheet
- (near R52) CS offset = 6.7mV for FCCM at no load
- (near R61) Fsw = 150 kHz
- CS offset = 6.7mV for FCCM at no load
- (near C59) OVPA=PGND(at VIN pin)-AGND=VIN=85V
  OVPB=CSB-AGND=VIN=65V (disabled in boost mode)
  OVP cannot monitor VOUT in this configuration

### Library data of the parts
C41 C44 = CMP-0006993-4: CAP, CERM, 1000 pF, 100 V, +/- 5%, C0G/NP0, 0603; PartNumber: C1608C0G2A102J080AA; Manufacturer: TDK; Polarized: N; Value: 1000pF; U/M: EA; Cap_F: 1nF; ESR_ohm: 0.0589; Value1: 0.0589 ohm; VDC_V: 100V; TaMin_C: -55°C; TaMax_C: 125°C; Cap_Case: 0603; AEC Category: Q200; SizeArea_mm2: 1.28; SizeAreaWB_mm2: 4.68; SizeX_mm: 1.6; SizeY_mm: 0.8; SizeZ_mm: 1
C42 C61 = CMP-0007467-4: as C13 on sheet PMP21943A-Bias
C43 C58 = CMP-0007469-4: CAP, CERM, 0.1 uF, 100 V, +/- 10%, X7R, 0603; Manufacturer: MuRata; Polarized: N; Value: 0.1uF; U/M: EA; Cap_F: 100nF; Value1: Unknown; VDC_V: 100V; TaMin_C: -55°C; TaMax_C: 125°C; Cap_Case: 0603; SizeArea_mm2: 1.28; SizeAreaWB_mm2: 4.68; SizeX_mm: 1.6; SizeY_mm: 0.8; SizeZ_mm: 1; AEC Category: Q200
C45 = CMP-0007891-2: as C3 on sheet PMP21943A-Bias
C46 C55 = CMP-0007398-4: CAP, CERM, 0.47 uF, 16 V, +/- 10%, X7R, 0603; Manufacturer: MuRata; Polarized: N; Value: 0.47uF; U/M: EA; Cap_F: 470nF; Value1: Unknown; VDC_V: 16V; TaMin_C: -55°C; TaMax_C: 125°C; Cap_Case: 0603; AEC Category: Q200; SizeArea_mm2: 1.28; SizeAreaWB_mm2: 4.68; SizeX_mm: 1.6; SizeY_mm: 0.8; SizeZ_mm: 1
C47 C48 C52 C56 C57 C59 C60 = CMP-0006841-4: CAP, CERM, 100 pF, 50 V, +/- 5%, C0G/NP0, 0603; PartNumber: C0603C101J5GACTU; Manufacturer: Kemet; Polarized: N; Value: 100pF; U/M: EA; Value1: Unknown; VDC_V: 50V; TaMin_C: -55°C; TaMax_C: 125°C; Cap_Case: 0603; AEC Category: Q200; SizeArea_mm2: 1.28; SizeAreaWB_mm2: 4.68; SizeX_mm: 1.6; SizeY_mm: 0.8; SizeZ_mm: 1
C49 = CMP-0007047-4: CAP, CERM, 0.22 uF, 50 V, +/- 10%, X7R, 0603; Manufacturer: TDK; Polarized: N; Value: 0.22uF; U/M: EA; Cap_F: 220nF; ESR_ohm: 0.021699; Value1: 0.021699 ohm; VDC_V: 50V; IRMS_A: 1.12496A; TaMin_C: -55°C; TaMax_C: 125°C; Cap_Case: 0603; SizeArea_mm2: 1.28; SizeAreaWB_mm2: 4.68; SizeX_mm: 1.6; SizeY_mm: 0.8; SizeZ_mm: 1; AEC Category: Q200
C50 = CMP-0007867-2: CAP, CERM, 2.2 uF, 16 V, +/- 10%, X7R, 0805; PartNumber: C2012X7R1C225K125AB; Manufacturer: TDK; Value: 2.2uF; U/M: EA; VDC_V: 16V; Polarized: N; Cap_F: 2.2µF; ESR_ohm: 4.9m; Value1: 0.0049 ohm; TaMin_C: -55°C; TaMax_C: 125°C; Cap_Case: 0805; AEC Category: Q200; SizeArea_mm2: 2.5; SizeAreaWB_mm2: 6.75; SizeX_mm: 2; SizeY_mm: 1.25; SizeZ_mm: 1.45
C51 = CMP-0007405-4: CAP, CERM, 1 uF, 25 V, +/- 10%, X7R, 0603; PartNumber: GRM188R71E105KA12D; Manufacturer: MuRata; Polarized: N; Value: 1uF; U/M: EA; Cap_F: 1µF; Value1: Unknown; VDC_V: 25V; TaMin_C: -55°C; TaMax_C: 125°C; Cap_Case: 0603; AEC Category: Q200; SizeArea_mm2: 1.28; SizeAreaWB_mm2: 4.68; SizeX_mm: 1.6; SizeY_mm: 0.8; SizeZ_mm: 1
C53 = CMP-0007047-4: CAP, CERM, 0.22 uF, 50 V, +/- 10%, X7R, 0603; PartNumber: C1608X7R1H224K080AB; Manufacturer: TDK; Polarized: N; Value: 0.22uF; U/M: EA; Cap_F: 220nF; ESR_ohm: 0.021699; Value1: 0.021699 ohm; VDC_V: 50V; IRMS_A: 1.12496A; TaMin_C: -55°C; TaMax_C: 125°C; Cap_Case: 0603; SizeArea_mm2: 1.28; SizeAreaWB_mm2: 4.68; SizeX_mm: 1.6; SizeY_mm: 0.8; SizeZ_mm: 1; AEC Category: Q200
C54 = CMP-0006727-4: CAP, CERM, 0.01 uF, 100 V, +/- 10%, X7R, 0603; PartNumber: 06031C103KAT2A; Manufacturer: AVX; Polarized: N; Value: 0.01uF; U/M: EA; Cap_F: 10nF; ESR_ohm: 0.098; Value1: 0.098 ohm; VDC_V: 100V; TaMin_C: -55°C; TaMax_C: 125°C; Cap_Case: 0603; SizeArea_mm2: 1.28; SizeAreaWB_mm2: 4.68; SizeX_mm: 1.6; SizeY_mm: 0.8; SizeZ_mm: 1; AEC Category: Q200
D8 D11 = CMP-0076957-3: as D2 on sheet PMP21943A-Bias
D9 D10 = CMP-0077034-2: as D1 on sheet PMP21943A-Bias
J8 J9 = CMP-0075483-1: Header, 100mil, 2x1, Gold, TH; PartNumber: HTSW-102-07-G-S; Manufacturer: Samtec; CNHeader: True; CT: False; Green_Lifecycle: Active; Green_REACh: Passed
NT2 = CMP-0078142-3: Single point connection between nets.
Q9 Q10 = CMP-0000771-1: as Q5 on sheet PMP21943A-Bias
R49 R51 = CMP-0021990-4: as R27 on sheet PMP21943A-Bias
R50 R68 = CMP-0022126-4: RES, 1.50 k, 1%, 0.1 W, AEC-Q200 Grade 0, 0603; Manufacturer: Vishay-Dale; Value: 1.50k; Res_ohm: 1.5k; Value_Code: 1k50; Power_W: 100mW; Value2: 0.1W; VDC_V: 75V; TempCo: 100 ppm/C; EIA_Code: E96; SizeArea_mm2: 1.28; SizeX_mm: 1.6; SizeY_mm: 0.8; SizeZ_mm: 1; AEC Category: Q200; AEC Qualified: Y; AEC Grade: 0
R52 R65 = CMP-0022371-4: RES, 3.01 k, 1%, 0.1 W, AEC-Q200 Grade 0, 0603; Manufacturer: Vishay-Dale; Power_W: 100mW; TempCo: 100 ppm/C; Value_Code: 3k01; Value: 3.01k; EIA_Code: E96; SizeX_mm: 1.6; SizeY_mm: 0.8; SizeZ_mm: 1; Value2: 0.1W; SizeArea_mm2: 1.28; AEC Qualified: Y; VDC_V: 75V; AEC Category: Q200; AEC Grade: 0
R53 R54 R60 = CMP-0022447-4: RES, 49.9 k, 1%, 0.1 W, AEC-Q200 Grade 0, 0603; PartNumber: CRCW060349K9FKEA; Manufacturer: Vishay-Dale; Value: 49.9k; Value_Code: 49k9; Power_W: 100mW; Value2: 0.1W; VDC_V: 75V; TempCo: 100 ppm/C; EIA_Code: E96; AEC Category: Q200; AEC Grade: 0; AEC Qualified: Y; SizeArea_mm2: 1.28; SizeX_mm: 1.6; SizeY_mm: 0.8; SizeZ_mm: 1
R55 = CMP-0021998-4: as R10 on sheet PMP21943A-Bias
R56 R57 = CMP-0022204-4: as R21 on sheet PMP21943A-Bias
R58 R63 = CMP-0025776-4: RES, 2.0, 5%, 0.1 W, AEC-Q200 Grade 0, 0603; PartNumber: CRCW06032R00JNEA; Manufacturer: Vishay-Dale; Value: 2.0; Res_ohm: 2; Value_Code: 2R00; Power_W: 100mW; Value2: 0.1W; VDC_V: 75V; TempCo: 200 ppm/C; EIA_Code: E24; AEC Category: Q200; AEC Qualified: Y; AEC Grade: 0; SizeArea_mm2: 1.28; SizeX_mm: 1.6; SizeY_mm: 0.8; SizeZ_mm: 1
R59 = CMP-0022066-4: RES, 15.0 k, 1%, 0.1 W, AEC-Q200 Grade 0, 0603; PartNumber: CRCW060315K0FKEA; Manufacturer: Vishay-Dale; Value: 15.0k; Res_ohm: 15k; Value_Code: 15k0; Power_W: 100mW; Value2: 0.1W; VDC_V: 75V; TempCo: 100 ppm/C; EIA_Code: E96; SizeArea_mm2: 1.28; SizeX_mm: 1.6; SizeY_mm: 0.8; SizeZ_mm: 1; AEC Category: Q200; AEC Qualified: Y; AEC Grade: 0
R61 = CMP-0022249-4: RES, 26.7 k, 1%, 0.1 W, AEC-Q200 Grade 0, 0603; PartNumber: CRCW060326K7FKEA; Manufacturer: Vishay-Dale; Value: 26.7k; Value_Code: 26k7; Power_W: 100mW; Value2: 0.1W; VDC_V: 75V; TempCo: 100 ppm/C; EIA_Code: E96; SizeArea_mm2: 1.28; SizeX_mm: 1.6; SizeY_mm: 0.8; SizeZ_mm: 1; AEC Category: Q200; AEC Qualified: Y; AEC Grade: 0
R62 = CMP-0022239-4: RES, 24.9, 1%, 0.1 W, AEC-Q200 Grade 0, 0603; Manufacturer: Vishay-Dale; Value: 24.9; Value_Code: 24R9; Power_W: 100mW; Value2: 0.1W; VDC_V: 75V; TempCo: 100 ppm/C; EIA_Code: E96; AEC Category: Q200; AEC Grade: 0; AEC Qualified: Y; SizeArea_mm2: 1.28; SizeX_mm: 1.6; SizeY_mm: 0.8; SizeZ_mm: 1
R64 = CMP-0022532-4: RES, 60.4 k, 1%, 0.1 W, AEC-Q200 Grade 0, 0603; Manufacturer: Vishay-Dale; Value: 60.4k; Value_Code: 60k4; Power_W: 100mW; Value2: 0.1W; VDC_V: 75V; TempCo: 100 ppm/C; EIA_Code: E96; AEC Category: Q200; AEC Qualified: Y; AEC Grade: 0; SizeArea_mm2: 1.28; SizeX_mm: 1.6; SizeY_mm: 0.8; SizeZ_mm: 1
R66 = CMP-0022418-4: RES, 42.2 k, 1%, 0.1 W, AEC-Q200 Grade 0, 0603; PartNumber: CRCW060342K2FKEA; Manufacturer: Vishay-Dale; Value: 42.2k; Value_Code: 42k2; Power_W: 100mW; Value2: 0.1W; VDC_V: 75V; TempCo: 100 ppm/C; EIA_Code: E96; SizeArea_mm2: 1.28; SizeX_mm: 1.6; SizeY_mm: 0.8; SizeZ_mm: 1; AEC Category: Q200; AEC Qualified: Y; AEC Grade: 0
R67 = CMP-0022098-4: RES, 18.7 k, 1%, 0.1 W, AEC-Q200 Grade 0, 0603; PartNumber: CRCW060318K7FKEA; Manufacturer: Vishay-Dale; Value: 18.7k; Value_Code: 18k7; Power_W: 100mW; Value2: 0.1W; VDC_V: 75V; TempCo: 100 ppm/C; EIA_Code: E96; SizeArea_mm2: 1.28; SizeX_mm: 1.6; SizeY_mm: 0.8; SizeZ_mm: 1; AEC Category: Q200; AEC Qualified: Y; AEC Grade: 0
TP2 = CMP-0055121-1: Terminal, Turret, TH, Triple; PartNumber: 1598-2; Manufacturer: Keystone; CompType: Turret Terminal; Green_Lifecycle: Active; Green_REACh: Passed; CNHeader: FALSE
U8 = CMP-0013575-3: Multiphase Bidirectional Current Controller, PHP0048C (HTQFP-48); Manufacturer: Texas Instruments; Alternate PartNumber: LM5170QPHPTQ1; CompType: IC; SizeArea_mm2: 81; SizeAreaWB_mm2: 121; SizeX_mm: 9; SizeZ_mm: 1.2; AEC Category: Q200; AEC Qualified: Y; Rating: Automotive
U9 = CMP-0013548-2: 4A/6A Isolated Dual-Channel Gate Driver, NPL0013A (VLGA-13); Manufacturer: Texas Instruments; SizeX_mm: 5; CompType: IC; SizeZ_mm: 1; SizeArea_mm2: 25; SizeAreaWB_mm2: 49; U/M: EA

## Sheet PMP21943A-Power2.SchDoc: Power Stage
size 431 x 279 mm; Date: Not shown in title block; ApprovedBy: Not shown in title block; CheckedBy: Not shown in title block; Author: Not shown in title block; CompanyName: Not shown in title block; Engineer: Not shown in title block; Organization: Not shown in title block; Address1: Not shown in title block; Address2: Not shown in title block; Address3: Not shown in title block; Address4: Not shown in title block; DocumentNumber: 6; Revision: Use project parameter SCH_Rev; SheetNumber: 6; SheetTotal: 7; PageSetup: Record=PageOptions¦CenterHorizontal=True¦CenterVertical=True¦PrintScale=0.62¦XCorrection=1.00¦YCorrection=1.00¦PrintKind=0¦BorderSize=5000000¦LeftOffset=0¦BottomOffset=0¦Orientation=2¦PaperLength=1000¦PaperWidth=1000¦Scale=100¦PaperSource=15¦PrintQuality=600¦MediaType=1¦DitherType=10¦PrintScaleMode=1¦PaperKind=Letter (8.5 x 11")¦PaperIndex=1
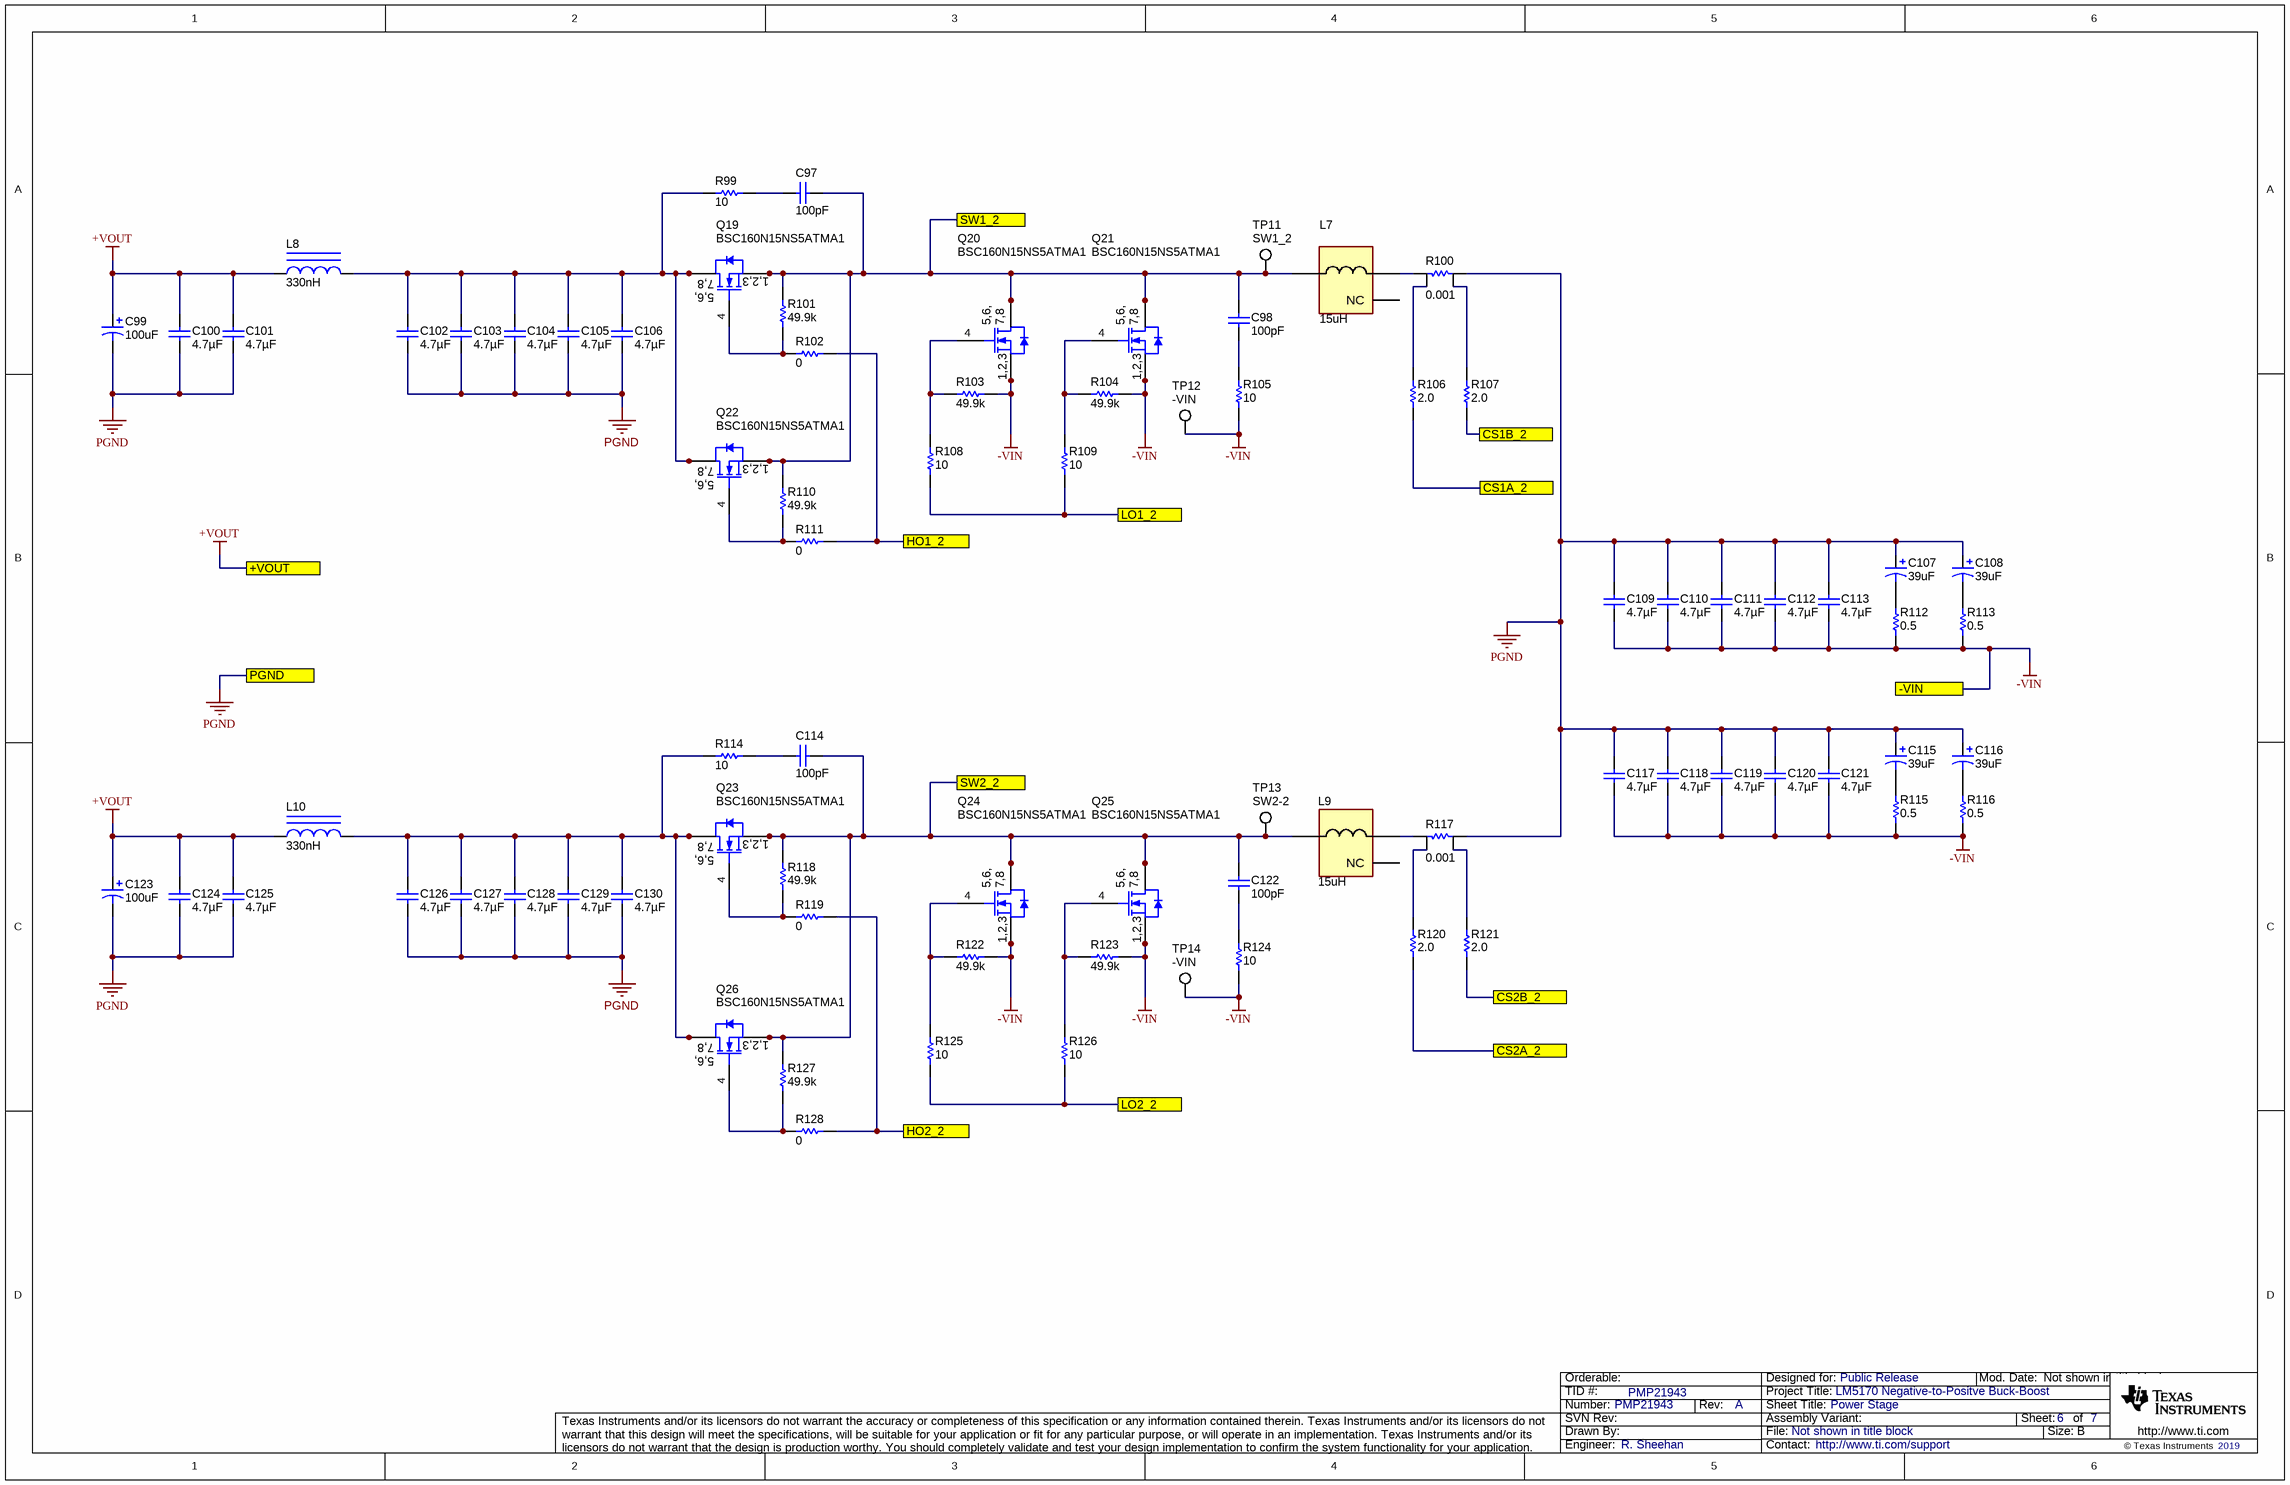
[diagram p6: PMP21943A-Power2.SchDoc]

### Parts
C97  ValueDisplayed: 100pF  [0805_HV]  (hidden comment: Capacitor)
C98  ValueDisplayed: 100pF  [0805_HV]  (hidden comment: Capacitor)
C99  ValueDisplayed: 100uF  [CR_1000x1270]  (hidden comment: Cap_Polarized)
C100  ValueDisplayed: 4.7µF  [1210_220L]  (hidden comment: GCM32DC72A475KE02L)
C101  ValueDisplayed: 4.7µF  [1210_220L]  (hidden comment: GCM32DC72A475KE02L)
C102  ValueDisplayed: 4.7µF  [1210_220L]  (hidden comment: GCM32DC72A475KE02L)
C103  ValueDisplayed: 4.7µF  [1210_220L]  (hidden comment: GCM32DC72A475KE02L)
C104  ValueDisplayed: 4.7µF  [1210_220L]  (hidden comment: GCM32DC72A475KE02L)
C105  ValueDisplayed: 4.7µF  [1210_220L]  (hidden comment: GCM32DC72A475KE02L)
C106  ValueDisplayed: 4.7µF  [1210_220L]  (hidden comment: GCM32DC72A475KE02L)
C107  ValueDisplayed: 39uF  [CR_800x1200]  (hidden comment: Cap_Polarized)
C108  ValueDisplayed: 39uF  [CR_800x1200]  (hidden comment: Cap_Polarized)
C109  ValueDisplayed: 4.7µF  [1210_220L]  (hidden comment: GCM32DC72A475KE02L)
C110  ValueDisplayed: 4.7µF  [1210_220L]  (hidden comment: GCM32DC72A475KE02L)
C111  ValueDisplayed: 4.7µF  [1210_220L]  (hidden comment: GCM32DC72A475KE02L)
C112  ValueDisplayed: 4.7µF  [1210_220L]  (hidden comment: GCM32DC72A475KE02L)
C113  ValueDisplayed: 4.7µF  [1210_220L]  (hidden comment: GCM32DC72A475KE02L)
C114  ValueDisplayed: 100pF  [0805_HV]  (hidden comment: Capacitor)
C115  ValueDisplayed: 39uF  [CR_800x1200]  (hidden comment: Cap_Polarized)
C116  ValueDisplayed: 39uF  [CR_800x1200]  (hidden comment: Cap_Polarized)
C117  ValueDisplayed: 4.7µF  [1210_220L]  (hidden comment: GCM32DC72A475KE02L)
C118  ValueDisplayed: 4.7µF  [1210_220L]  (hidden comment: GCM32DC72A475KE02L)
C119  ValueDisplayed: 4.7µF  [1210_220L]  (hidden comment: GCM32DC72A475KE02L)
C120  ValueDisplayed: 4.7µF  [1210_220L]  (hidden comment: GCM32DC72A475KE02L)
C121  ValueDisplayed: 4.7µF  [1210_220L]  (hidden comment: GCM32DC72A475KE02L)
C122  ValueDisplayed: 100pF  [0805_HV]  (hidden comment: Capacitor)
C123  ValueDisplayed: 100uF  [CR_1000x1270]  (hidden comment: Cap_Polarized)
C124  ValueDisplayed: 4.7µF  [1210_220L]  (hidden comment: GCM32DC72A475KE02L)
C125  ValueDisplayed: 4.7µF  [1210_220L]  (hidden comment: GCM32DC72A475KE02L)
C126  ValueDisplayed: 4.7µF  [1210_220L]  (hidden comment: GCM32DC72A475KE02L)
C127  ValueDisplayed: 4.7µF  [1210_220L]  (hidden comment: GCM32DC72A475KE02L)
C128  ValueDisplayed: 4.7µF  [1210_220L]  (hidden comment: GCM32DC72A475KE02L)
C129  ValueDisplayed: 4.7µF  [1210_220L]  (hidden comment: GCM32DC72A475KE02L)
C130  ValueDisplayed: 4.7µF  [1210_220L]  (hidden comment: GCM32DC72A475KE02L)
L7  value 15uH  [FP-7443641500_SMT_IND_28MM0_19MM4-MFG]  (hidden comment: 7443641500)
L8  ValueDisplayed: 330nH  [VLBU1007090]  (hidden comment: VLBU1007090T-R33L)
L9  value 15uH  [FP-7443641500_SMT_IND_28MM0_19MM4-MFG]  (hidden comment: 7443641500)
L10  ValueDisplayed: 330nH  [VLBU1007090]  (hidden comment: VLBU1007090T-R33L)
Q19  BSC160N15NS5ATMA1  [PG-TDSON-8]
Q20  BSC160N15NS5ATMA1  [PG-TDSON-8]
Q21  BSC160N15NS5ATMA1  [PG-TDSON-8]
Q22  BSC160N15NS5ATMA1  [PG-TDSON-8]
Q23  BSC160N15NS5ATMA1  [PG-TDSON-8]
Q24  BSC160N15NS5ATMA1  [PG-TDSON-8]
Q25  BSC160N15NS5ATMA1  [PG-TDSON-8]
Q26  BSC160N15NS5ATMA1  [PG-TDSON-8]
R99  ValueDisplayed: 10  [2010]  (hidden comment: Resistor)
R100  ValueDisplayed: 0.001  [RES_WSL2726]  (hidden comment: Resistor_Kelvin)
R101  ValueDisplayed: 49.9k  [0603L]  (hidden comment: Resistor)
R102  ValueDisplayed: 0  [0603L]  (hidden comment: Resistor)
R103  ValueDisplayed: 49.9k  [0603L]  (hidden comment: Resistor)
R104  ValueDisplayed: 49.9k  [0603L]  (hidden comment: Resistor)
R105  ValueDisplayed: 10  [2010]  (hidden comment: Resistor)
R106  ValueDisplayed: 2.0  [0603L]  (hidden comment: Resistor)
R107  ValueDisplayed: 2.0  [0603L]  (hidden comment: Resistor)
R108  ValueDisplayed: 10  [0603L]  (hidden comment: CRCW060310R0JNEA)
R109  ValueDisplayed: 10  [0603L]  (hidden comment: CRCW060310R0JNEA)
R110  ValueDisplayed: 49.9k  [0603L]  (hidden comment: Resistor)
R111  ValueDisplayed: 0  [0603L]  (hidden comment: Resistor)
R112  ValueDisplayed: 0.5  [2010]  (hidden comment: Resistor)
R113  ValueDisplayed: 0.5  [2010]  (hidden comment: Resistor)
R114  ValueDisplayed: 10  [2010]  (hidden comment: Resistor)
R115  ValueDisplayed: 0.5  [2010]  (hidden comment: Resistor)
R116  ValueDisplayed: 0.5  [2010]  (hidden comment: Resistor)
R117  ValueDisplayed: 0.001  [RES_WSL2726]  (hidden comment: Resistor_Kelvin)
R118  ValueDisplayed: 49.9k  [0603L]  (hidden comment: Resistor)
R119  ValueDisplayed: 0  [0603L]  (hidden comment: Resistor)
R120  ValueDisplayed: 2.0  [0603L]  (hidden comment: Resistor)
R121  ValueDisplayed: 2.0  [0603L]  (hidden comment: Resistor)
R122  ValueDisplayed: 49.9k  [0603L]  (hidden comment: Resistor)
R123  ValueDisplayed: 49.9k  [0603L]  (hidden comment: Resistor)
R124  ValueDisplayed: 10  [2010]  (hidden comment: Resistor)
R125  ValueDisplayed: 10  [0603L]  (hidden comment: CRCW060310R0JNEA)
R126  ValueDisplayed: 10  [0603L]  (hidden comment: CRCW060310R0JNEA)
R127  ValueDisplayed: 49.9k  [0603L]  (hidden comment: Resistor)
R128  ValueDisplayed: 0  [0603L]  (hidden comment: Resistor)
TP11  SW1_2  [Testpoint_Keystone_Miniature]
TP12  -VIN  [Testpoint_Keystone_Miniature]
TP13  SW2-2  [Testpoint_Keystone_Miniature]
TP14  -VIN  [Testpoint_Keystone_Miniature]

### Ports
+VOUT, -VIN, CS1A_2, CS1B_2, CS2A_2, CS2B_2, HO1_2, HO2_2, LO1_2, LO2_2, PGND, SW1_2, SW2_2

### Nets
+VOUT: C99.1(+) C100.1 C101.1 C123.1(+) C124.1 C125.1 L8.1 L10.1 ; port +VOUT
-VIN: C109.2 C110.2 C111.2 C112.2 C113.2 C117.2 C118.2 C119.2 C120.2 C121.2 Q20.1(S) Q20.2(S) Q20.3(S) Q21.1(S) Q21.2(S) Q21.3(S) Q24.1(S) Q24.2(S) Q24.3(S) Q25.1(S) Q25.2(S) Q25.3(S) R103.2 R104.2 R105.1 R112.1 R113.1 R115.1 R116.1 R122.2 R123.2 R124.1 TP12.1 TP14.1 ; port -VIN
PGND: C99.2(-) C100.2 C101.2 C102.2 C103.2 C104.2 C105.2 C106.2 C107.1(+) C108.1(+) C109.1 C110.1 C111.1 C112.1 C113.1 C115.1(+) C116.1(+) C117.1 C118.1 C119.1 C120.1 C121.1 C123.2(-) C124.2 C125.2 C126.2 C127.2 C128.2 C129.2 C130.2 R100.2 R117.2 ; port PGND
CS1A_2: R106.1 ; port CS1A_2
CS1B_2: R107.1 ; port CS1B_2
CS2A_2: R120.1 ; port CS2A_2
CS2B_2: R121.1 ; port CS2B_2
HO1_2: R102.1 R111.1 ; port HO1_2
HO2_2: R119.1 R128.1 ; port HO2_2
LO1_2: R108.1 R109.1 ; port LO1_2
LO2_2: R125.1 R126.1 ; port LO2_2
SW1_2: C97.1 C98.1 L7.1 Q19.1(S) Q19.2(S) Q19.3(S) Q20.5(D) Q20.6(D) Q20.7(D) Q20.8(D) Q20.9(D) Q21.5(D) Q21.6(D) Q21.7(D) Q21.8(D) Q21.9(D) Q22.1(S) Q22.2(S) Q22.3(S) R101.1 R110.1 TP11.1 ; port SW1_2
SW2_2: C114.1 C122.1 L9.1 Q23.1(S) Q23.2(S) Q23.3(S) Q24.5(D) Q24.6(D) Q24.7(D) Q24.8(D) Q24.9(D) Q25.5(D) Q25.6(D) Q25.7(D) Q25.8(D) Q25.9(D) Q26.1(S) Q26.2(S) Q26.3(S) R118.2 R127.2 TP13.1 ; port SW2_2
NetC97_2: C97.2 R99.2
NetC98_2: C98.2 R105.2
NetC102_1: C102.1 C103.1 C104.1 C105.1 C106.1 L8.2 Q19.5(D) Q19.6(D) Q19.7(D) Q19.8(D) Q19.9(D) Q22.5(D) Q22.6(D) Q22.7(D) Q22.8(D) Q22.9(D) R99.1
NetC107_2: C107.2(-) R112.2
NetC108_2: C108.2(-) R113.2
NetC114_2: C114.2 R114.2
NetC115_2: C115.2(-) R115.2
NetC116_2: C116.2(-) R116.2
NetC122_2: C122.2 R124.2
NetC126_1: C126.1 C127.1 C128.1 C129.1 C130.1 L10.2 Q23.5(D) Q23.6(D) Q23.7(D) Q23.8(D) Q23.9(D) Q26.5(D) Q26.6(D) Q26.7(D) Q26.8(D) Q26.9(D) R114.1
NetL7_2: L7.2 R100.1
NetL9_2: L9.2 R117.1
NetQ19_4: Q19.4(G) R101.2 R102.2
NetQ20_4: Q20.4(G) R103.1 R108.2
NetQ21_4: Q21.4(G) R104.1 R109.2
NetQ22_4: Q22.4(G) R110.2 R111.2
NetQ23_4: Q23.4(G) R118.1 R119.2
NetQ24_4: Q24.4(G) R122.1 R125.2
NetQ25_4: Q25.4(G) R123.1 R126.2
NetQ26_4: Q26.4(G) R127.1 R128.2
NetR100_3: R100.3 R106.2
NetR100_4: R100.4 R107.2
NetR117_3: R117.3 R120.2
NetR117_4: R117.4 R121.2

Not connected (* = marked no-connect by the designer): L7 3(NC); L9 3(NC)

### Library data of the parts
C97 C98 C114 C122 = CMP-0007518-2: CAP, CERM, 100 pF, 100 V, +/- 10%, C0G/NP0, 0805; PartNumber: 08051A101KAT2A; Manufacturer: AVX; Polarized: N; Value: 100pF; U/M: EA; ESR_ohm: 3.56d; Value1: 0.356 ohm; VDC_V: 100V; TaMin_C: -55°C; TaMax_C: 125°C; Cap_Case: 0805; AEC Category: Q200; SizeArea_mm2: 2.5; SizeAreaWB_mm2: 6.75; SizeX_mm: 2; SizeY_mm: 1.25; SizeZ_mm: 1.45
C99 C123 = CMP-0012274-3: CAP, Aluminum Polymer, 100 uF, 63 V, +/- 20%, 0.024 ohm, SMD, 2-Leads, Dia 10.5mm, Pin Spacing 8mm SMD; Manufacturer: Nichicon; PartNumber: PCR1J101MCL1GS; CompType: Capacitor; ESR_ohm: 0.024; VDC_V: 63V; Value: 100uF; Polarized: Y; Cap_F: 100µF; IRMS_A: 3A; TaMin_C: -55°C; TaMax_C: 125°C; Cap_Case: 10x12.7mm; AEC Category: Q200; AEC Qualified: N
C100 C101 C109 C117 C124 C125 = CMP-0082268-1: CAP, CERM, 4.7 µF, 100 V,+/- 10%, X7S, AEC-Q200 Grade 1, 1210; Manufacturer: MuRata; U/M: EA; ESR_ohm: 1m; VDC_V: 100V; Value: 4.7uF; Polarized: N; Value1: 0.001 ohm; IRMS_A: 6A; TaMin_C: -55°C; TaMax_C: 125°C; Cap_Case: 1210; AEC Category: Q200; AEC Qualified: Y; AEC Grade: 1; SizeArea_mm2: 8; SizeAreaWB_mm2: 14.7; SizeX_mm: 3.2; SizeY_mm: 2.5; SizeZ_mm: 2.2
C102-C106 C110-C113 C118-C121 C126-C130 = CMP-0082268-1: CAP, CERM, 4.7 µF, 100 V,+/- 10%, X7S, AEC-Q200 Grade 1, 1210; Manufacturer: MuRata; Polarized: N; Value: 4.7uF; U/M: EA; ESR_ohm: 1m; Value1: 0.001 ohm; VDC_V: 100V; IRMS_A: 6A; TaMin_C: -55°C; TaMax_C: 125°C; Cap_Case: 1210; AEC Category: Q200; AEC Qualified: Y; AEC Grade: 1; SizeArea_mm2: 8; SizeAreaWB_mm2: 14.7; SizeX_mm: 3.2; SizeY_mm: 2.5; SizeZ_mm: 2.2
C107 C108 C115 C116 = CMP-0012276-3: CAP, Aluminum Polymer, 39 uF, 80 V, +/- 20%, 0.035 ohm, D8xL12mm SMD; PartNumber: PCR1K390MCL1GS; Manufacturer: Nichicon; Polarized: Y; CompType: Capacitor; Value: 39uF; Cap_F: 39µF; VDC_V: 80V; ESR_ohm: 0.035; IRMS_A: 1.6A; TaMin_C: -55°C; TaMax_C: 125°C; Cap_Case: 8x12mm; AEC Category: Q200; AEC Qualified: N
L7 L9 = CMP-0087002-1: Surface Mount Power Inductor, WE-HCF Series, 15 H, 15%, Shielded, 2400 ohm, 30 A; Manufacturer: Wurth Electronics; Imax_A: 30A; Isat: 26A; Material: Ferrite; SizeZ_mm: 18.5mm; AEC Qualified: No; Symbol Name: SYM-7443641500
L8 L10 = CMP-0085710-1: Inductor, Shielded, Ferrite, 330 nH, 39 A, 0.000198 ohm, SMD; Manufacturer: TDK; Value: 330nH; Imax_A: 39A; Irms: 70A @ 40C rise; Isat: 39A @ 20% inductance drop; DCR_ohm: 198µ; SizeAreaWB_mm2: 108; SizeArea_mm2: 70; SizeX_mm: 10; SizeY_mm: 7; SizeZ_mm: 9; AEC Category: Q200; AEC Qualified: N
Q19-Q26 = CMP-0067566-1: MOSFET, N-CH, 150 V, 56 A, PG-TDSON-8; Manufacturer: Infineon Technologies; Alternate Manufacturer: None; U/M: EA; VdsMax_V: 150V; ChType: N; Value: 150V; Value1: ? ohm; Value2: 19 nC; QgTyp_nC: 19.0; Vgs_V: 20V; IdsMax_A: 56A; SizeAreaWB_mm2: 55.131; SizeArea_mm2: 29.351; SizeX_mm: 5.99; SizeY_mm: 4.9; SizeZ_mm: 1.12; AEC Category: Q101
R99 R105 R114 R124 = CMP-0016049-3: RES, 10, 5%, 0.75 W, AEC-Q200 Grade 0, 2010; PartNumber: CRCW201010R0JNEF; Manufacturer: Vishay-Dale; Value: 10; Value_Code: 10R0; Power_W: 750mW; Value2: 0.75W; VDC_V: 400V; TempCo: 200 ppm/C; EIA_Code: E24; SizeArea_mm2: 12.5; SizeX_mm: 5; SizeY_mm: 2.5; SizeZ_mm: 1.66; AEC Category: Q200; AEC Qualified: Y; AEC Grade: 0
R100 R117 = CMP-0015287-2: RES, 0.001, 1%, 3 W, 6.6x3x6.9mm; Manufacturer: Vishay-Dale; PartNumber: WSL27261L000FEB; U/M: EA; Value: 0.001; TempCo: 75 ppm/C; Power_W: 3W; Res_ohm: 1m; Value_Code: 1L000; EIA_Code: E96; AEC Category: Q200
R101 R103 R104 R110 R118 R122 R123 R127 = CMP-0022447-4: RES, 49.9 k, 1%, 0.1 W, AEC-Q200 Grade 0, 0603; PartNumber: CRCW060349K9FKEA; Manufacturer: Vishay-Dale; Value: 49.9k; Value_Code: 49k9; Power_W: 100mW; Value2: 0.1W; VDC_V: 75V; TempCo: 100 ppm/C; EIA_Code: E96; SizeArea_mm2: 1.28; SizeX_mm: 1.6; SizeY_mm: 0.8; SizeZ_mm: 1; AEC Category: Q200; AEC Qualified: Y; AEC Grade: 0
R102 R111 R119 R128 = CMP-0025697-4: as R18 on sheet PMP21943A-Bias
R106 R107 R120 R121 = CMP-0025776-4: as R58 on sheet PMP21943A-Controller2
R108 R109 R125 R126 = CMP-0025703-4: RES, 10, 5%, 0.1 W, AEC-Q200 Grade 0, 0603; Manufacturer: Vishay-Dale; Value: 10; Value_Code: 10R0; Power_W: 100mW; Value2: 0.1W; VDC_V: 75V; TempCo: 200 ppm/C; EIA_Code: E24; SizeArea_mm2: 1.28; SizeX_mm: 1.6; SizeY_mm: 0.8; SizeZ_mm: 1; AEC Category: Q200; AEC Qualified: Y; AEC Grade: 0
R112 R113 R115 R116 = CMP-0016530-2: RES, 0.5, 1%, 1 W, 2010; PartNumber: CSRN2010FKR500; Manufacturer: Stackpole Electronics Inc; Value: 0.5; Res_ohm: 5d; Value_Code: R500; Power_W: 1W; TempCo: 250 ppm/C; U/M: EA; SizeArea_mm2: 12.5; SizeX_mm: 5; SizeY_mm: 2.5; SizeZ_mm: 1.66; AEC Category: Q200
TP11-TP14 = CMP-0055152-1: Test Point, Miniature, SMT; Manufacturer: Keystone; Green_Lifecycle: Active; Green_REACh: Passed; CNHeader: FALSE; CT: TRUE

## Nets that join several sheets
+VOUT: PMP21943A-Power1 (11 pins), PMP21943A-Bias (R12.1), PMP21943A-Power2 (8 pins)
-VIN: PMP21943A-Controller1 (7 pins), PMP21943A-Power1 (35 pins), PMP21943A-Bias (9 pins), PMP21943A-Controller2 (7 pins), PMP21943A-Power2 (34 pins)
AGND: PMP21943A-Controller1 (35 pins), PMP21943A-Bias (22 pins), PMP21943A-Controller2 (33 pins)
PGND: PMP21943A-Controller1 (C24.1 U6.6), PMP21943A-Power1 (39 pins), PMP21943A-Bias (10 pins), PMP21943A-Controller2 (C45.1 U8.6), PMP21943A-Power2 (32 pins)
V5: PMP21943A-Controller1 (R33.2 R34.2), PMP21943A-Bias (9 pins), PMP21943A-Controller2 (R53.2 R54.2)
V10: PMP21943A-Controller1 (11 pins), PMP21943A-Bias (6 pins), PMP21943A-Controller2 (11 pins)
CS1A_1: PMP21943A-Controller1 (C25.1 C26.1 R32.1 U6.36), PMP21943A-Power1 (R76.1)
CS1A_2: PMP21943A-Controller2 (C46.1 C47.1 R52.1 U8.36), PMP21943A-Power2 (R106.1)
CS1B_1: PMP21943A-Controller1 (C25.2 C27.1 U6.35), PMP21943A-Power1 (R77.1)
CS1B_2: PMP21943A-Controller2 (C46.2 C48.1 U8.35), PMP21943A-Power2 (R107.1)
CS2A_1: PMP21943A-Controller1 (C34.2 C36.1 R45.2 U6.1), PMP21943A-Power1 (R90.1)
CS2A_2: PMP21943A-Controller2 (C55.2 C57.1 R65.2 U8.1), PMP21943A-Power2 (R120.1)
CS2B_1: PMP21943A-Controller1 (C34.1 C35.1 U6.2), PMP21943A-Power1 (R91.1)
CS2B_2: PMP21943A-Controller2 (C55.1 C56.1 U8.2), PMP21943A-Power2 (R121.1)
ENABLE: PMP21943A-Controller1 (U6.10), PMP21943A-Bias (J2.1 Q5.1 R10.1 R18.2), PMP21943A-Controller2 (U8.10)
HO1_1: PMP21943A-Controller1 (U7.12), PMP21943A-Power1 (R72.1 R81.1)
HO1_2: PMP21943A-Controller2 (U9.12), PMP21943A-Power2 (R102.1 R111.1)
HO2_1: PMP21943A-Controller1 (U7.9), PMP21943A-Power1 (R89.1 R98.1)
HO2_2: PMP21943A-Controller2 (U9.9), PMP21943A-Power2 (R119.1 R128.1)
IMON: PMP21943A-Controller1 (D4.1 D7.1), PMP21943A-Bias (C15.1 R25.2 R28.2 U4.4), PMP21943A-Controller2 (D8.1 D11.1)
ISETA: PMP21943A-Controller1 (C31.1 U6.45), PMP21943A-Bias (R20.1 R22.1 R26.1), PMP21943A-Controller2 (C52.1 U8.45)
LO1_1: PMP21943A-Controller1 (Q7.1 U6.20), PMP21943A-Power1 (R78.1 R79.1)
LO1_2: PMP21943A-Controller2 (Q9.1 U8.20), PMP21943A-Power2 (R108.1 R109.1)
LO2_1: PMP21943A-Controller1 (Q8.1 U6.17), PMP21943A-Power1 (R95.1 R96.1)
LO2_2: PMP21943A-Controller2 (Q10.1 U8.17), PMP21943A-Power2 (R125.1 R126.1)
nFAULT: PMP21943A-Controller1 (U6.27), PMP21943A-Bias (R24.1), PMP21943A-Controller2 (U8.27)
SW1_1: PMP21943A-Controller1 (C28.1 U7.11), PMP21943A-Power1 (22 pins)
SW1_2: PMP21943A-Controller2 (C49.1 U9.11), PMP21943A-Power2 (22 pins)
SW2_1: PMP21943A-Controller1 (C32.2 U7.8), PMP21943A-Power1 (22 pins)
SW2_2: PMP21943A-Controller2 (C53.2 U9.8), PMP21943A-Power2 (22 pins)
SYNC: PMP21943A-Controller1 (R35.1 U6.41), PMP21943A-Controller2 (U8.40)
Vneg10: PMP21943A-Controller1 (R32.2 R45.1), PMP21943A-Bias (C1.1 D1.2), PMP21943A-Controller2 (R52.2 R65.1)

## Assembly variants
1200W: not fitted R24
700W: not fitted Q13 Q14 Q17 Q18 Q21 Q22 Q25 Q26 R24 R74 R79 R80 R81 R93 R96 R97 R98 R104 R109 R110 R111 R123 R126 R127 R128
